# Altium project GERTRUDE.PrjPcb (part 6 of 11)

## Sheet AUDIO_CODEC.SchDoc: AUDIO CODEC
size A3; Author: Silvio Navaretti; CompanyName: ARDUINO; DrawnBy: Silvio Navaretti; Engineer: Silvio Navaretti; Organization: ARDUINO; SheetNumber: 47; SheetTotal: 51; RevAuthor: Silvio Navaretti
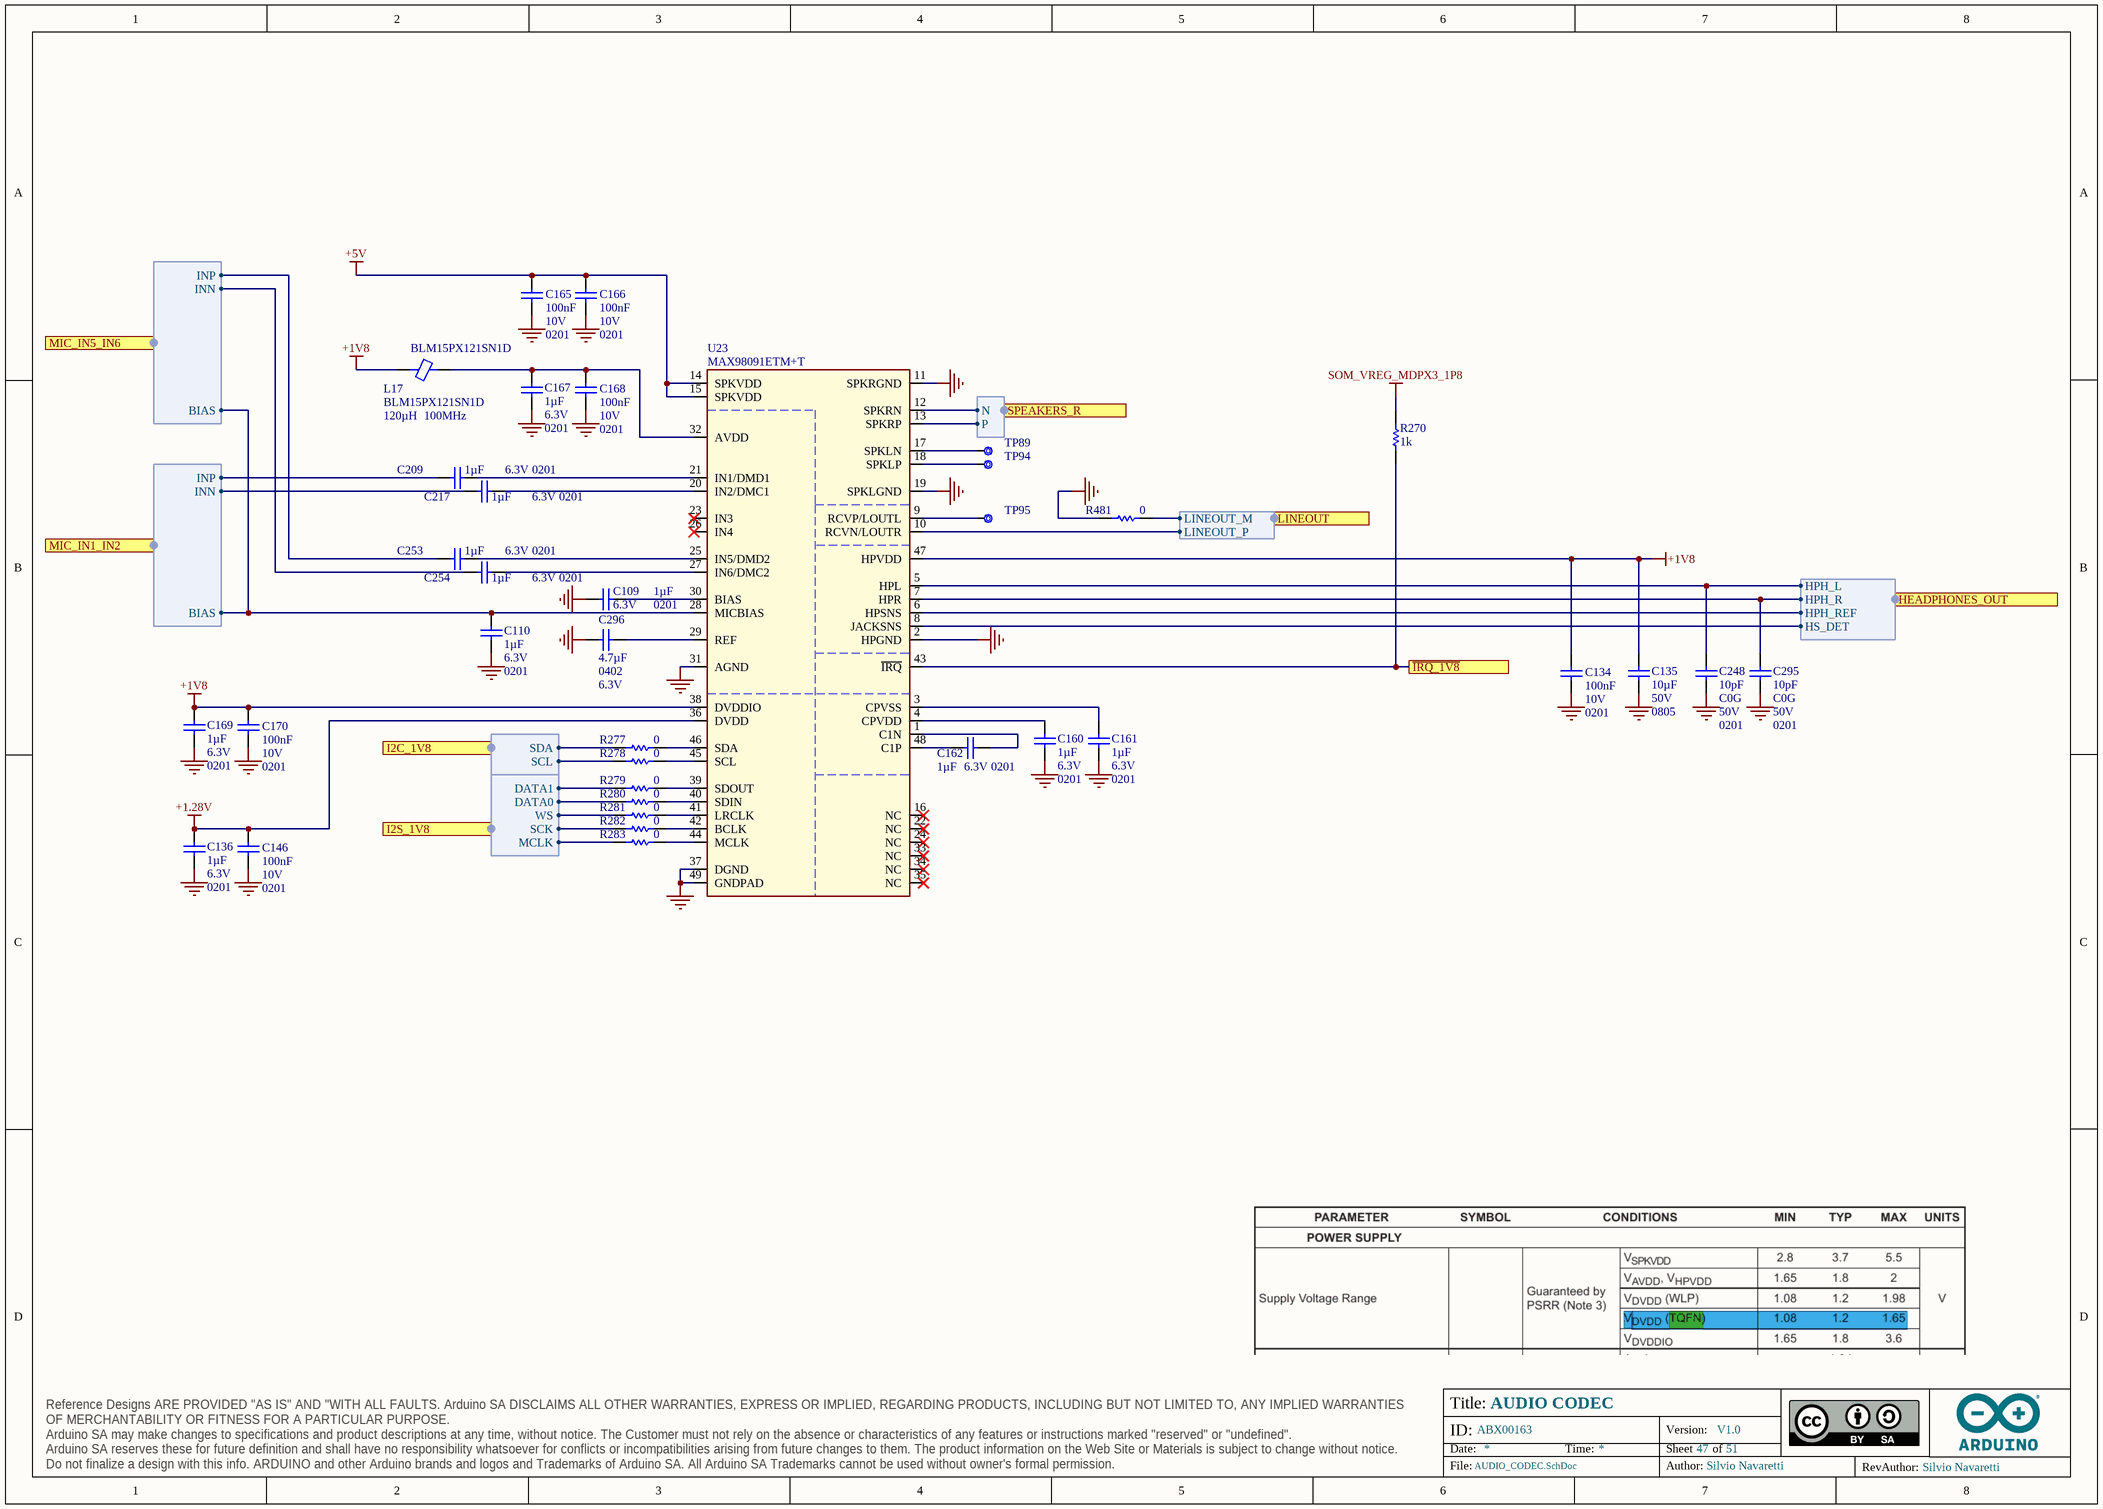
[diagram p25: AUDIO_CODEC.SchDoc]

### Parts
C109  value 1µF  Voltage: 6.3V  Case Code (Imperial): 0201  [CAP-0201]  (hidden comment: GRM033R60J105MEA2D)
C110  value 1µF  Voltage: 6.3V  Case Code (Imperial): 0201  [CAP-0201]  (hidden comment: GRM033R60J105MEA2D)
C134  value 100nF  Voltage: 10V  Case Code (Imperial): 0201  [CAP-0201]  (hidden comment: CL03A104KP3NNNC)
C135  value 10µF  Voltage: 50V  Case Code (Imperial): 0805  [CAP-0805]  (hidden comment: GRM21BR61H106ME43L)
C136  value 1µF  Voltage: 6.3V  Case Code (Imperial): 0201  [CAP-0201]  (hidden comment: GRM033R60J105MEA2D)
C146  value 100nF  Voltage: 10V  Case Code (Imperial): 0201  [CAP-0201]  (hidden comment: CL03A104KP3NNNC)
C160  value 1µF  Voltage: 6.3V  Case Code (Imperial): 0201  [CAP-0201]  (hidden comment: GRM033R60J105MEA2D)
C161  value 1µF  Voltage: 6.3V  Case Code (Imperial): 0201  [CAP-0201]  (hidden comment: GRM033R60J105MEA2D)
C162  value 1µF  Voltage: 6.3V  Case Code (Imperial): 0201  [CAP-0201]  (hidden comment: GRM033R60J105MEA2D)
C165  value 100nF  Voltage: 10V  Case Code (Imperial): 0201  [CAP-0201]  (hidden comment: CL03A104KP3NNNC)
C166  value 100nF  Voltage: 10V  Case Code (Imperial): 0201  [CAP-0201]  (hidden comment: CL03A104KP3NNNC)
C167  value 1µF  Voltage: 6.3V  Case Code (Imperial): 0201  [CAP-0201]  (hidden comment: GRM033R60J105MEA2D)
C168  value 100nF  Voltage: 10V  Case Code (Imperial): 0201  [CAP-0201]  (hidden comment: CL03A104KP3NNNC)
C169  value 1µF  Voltage: 6.3V  Case Code (Imperial): 0201  [CAP-0201]  (hidden comment: GRM033R60J105MEA2D)
C170  value 100nF  Voltage: 10V  Case Code (Imperial): 0201  [CAP-0201]  (hidden comment: CL03A104KP3NNNC)
C209  value 1µF  Voltage: 6.3V  Case Code (Imperial): 0201  [CAP-0201]  (hidden comment: GRM033R60J105MEA2D)
C217  value 1µF  Voltage: 6.3V  Case Code (Imperial): 0201  [CAP-0201]  (hidden comment: GRM033R60J105MEA2D)
C248  value 10pF  Dielectric: C0G  Voltage: 50V  Case Code (Imperial): 0201  [CAP-0201]  (hidden comment: CC0201GRNPO9BN100)
C253  value 1µF  Voltage: 6.3V  Case Code (Imperial): 0201  [CAP-0201]  (hidden comment: GRM033R60J105MEA2D)
C254  value 1µF  Voltage: 6.3V  Case Code (Imperial): 0201  [CAP-0201]  (hidden comment: GRM033R60J105MEA2D)
C295  value 10pF  Dielectric: C0G  Voltage: 50V  Case Code (Imperial): 0201  [CAP-0201]  (hidden comment: CC0201GRNPO9BN100)
C296  value 4.7µF  Case Code (Imperial): 0402  Voltage: 6.3V  [CAP-0402]  (hidden comment: C1005A475M6R3NT)
L17  BLM15PX121SN1D  Inductance: 120µH  Test Frequency: 100MHz  [L-0402]
R270  value 1k  [RES-0201]  (hidden comment: RC0201FR-071KL)
R277  value 0  [RES-0201]  (hidden comment: CRCW02010000Z0ED)
R278  value 0  [RES-0201]  (hidden comment: CRCW02010000Z0ED)
R279  value 0  [RES-0201]  (hidden comment: CRCW02010000Z0ED)
R280  value 0  [RES-0201]  (hidden comment: CRCW02010000Z0ED)
R281  value 0  [RES-0201]  (hidden comment: CRCW02010000Z0ED)
R282  value 0  [RES-0201]  (hidden comment: CRCW02010000Z0ED)
R283  value 0  [RES-0201]  (hidden comment: CRCW02010000Z0ED)
R481  value 0  [RES-0201]  (hidden comment: CRCW02010000Z0ED)
TP89  Test point 1.00mm  [TP-1.00MM]  (value not drawn)  (no BOM)
TP94  Test point 1.00mm  [TP-1.00MM]  (value not drawn)  (no BOM)
TP95  Test point 1.00mm  [TP-1.00MM]  (value not drawn)  (no BOM)
U23  MAX98091ETM+T  [QFN127P600-8N]

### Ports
HEADPHONES_OUT (harness HEADPHONES), I2C_1V8 (harness I2C), I2S_1V8 (harness SOM_MD_I2S_QUA), LINEOUT (harness LINEOUT), MIC_IN1_IN2 (harness MIC), MIC_IN5_IN6 (harness MIC), SPEAKERS_R (harness SPEAKERS), ~{IRQ_1V8}

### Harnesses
I2C: SDA, SCL
HEADPHONES: HPH_L, HPH_R, HPH_REF, HS_DET
MIC: INP, INN, BIAS
SPEAKERS: N, P
SOM_MD_I2S_QUA: SCK, WS, DATA0, DATA1, MCLK
LINEOUT: LINEOUT_P, LINEOUT_M

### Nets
+1.28V: C136.2 C146.2 U23.36(DVDD)
+1V8: C134.2 C135.1 C169.2 C170.2 L17.1 U23.38(DVDDIO) U23.47(HPVDD)
+5V: C165.2 C166.2 U23.14(SPKVDD) U23.15(SPKVDD)
GND: C109.1 C110.1 C134.1 C135.2 C136.1 C146.1 C160.1 C161.1 C165.1 C166.1 C167.1 C168.1 C169.1 C170.1 C248.1 C295.1 C296.2 R481.1 U23.2(HPGND) U23.11(SPKRGND) U23.19(SPKLGND) U23.31(AGND) U23.37(DGND) U23.49(GNDPAD)
SOM_VREG_MDPX3_1P8: R270.2
MD_GPIO_16: R270.1 U23.43(~{IRQ}) ; port ~{IRQ_1V8}
MD_GPIO_45: R277.1 ; port I2C_1V8.SDA
MD_GPIO_46: R278.1 ; port I2C_1V8.SCL
MD_LPASS_GPIO_110: R282.1 ; port I2S_1V8.SCK
MD_LPASS_GPIO_111: R281.1 ; port I2S_1V8.WS
MD_LPASS_GPIO_112: R280.1 ; port I2S_1V8.DATA0
MD_LPASS_GPIO_113: R279.1 ; port I2S_1V8.DATA1
MD_LPASS_GPIO_115: R283.1 ; port I2S_1V8.MCLK
MIC_IN5_IN6.BIAS: C110.2 U23.28(MICBIAS) ; port MIC_IN1_IN2.BIAS, port MIC_IN5_IN6.BIAS
MIC_IN5_IN6.INN: C254.2 ; port MIC_IN5_IN6.INN
MIC_IN5_IN6.INP: C253.2 ; port MIC_IN5_IN6.INP
NetC109_2: C109.2 U23.30(BIAS)
NetC160_2: C160.2 U23.4(CPVDD)
NetC161_2: C161.2 U23.3(CPVSS)
NetC162_1: C162.1 U23.1(C1N)
NetC162_2: C162.2 U23.48(C1P)
NetC167_2: C167.2 C168.2 L17.2 U23.32(AVDD)
NetC209_1: C209.1 U23.21(IN1/DMD1)
NetC209_2: C209.2 ; port MIC_IN1_IN2.INP
NetC217_1: C217.1 U23.20(IN2/DMC1)
NetC217_2: C217.2 ; port MIC_IN1_IN2.INN
NetC248_2: C248.2 U23.5(HPL) ; port HEADPHONES_OUT.HPH_L
NetC253_1: C253.1 U23.25(IN5/DMD2)
NetC254_1: C254.1 U23.27(IN6/DMC2)
NetC295_2: C295.2 U23.7(HPR) ; port HEADPHONES_OUT.HPH_R
NetC296_1: C296.1 U23.29(REF)
NetD103_1: U23.13(SPKRP) ; port SPEAKERS_R.P
NetD103_2: U23.12(SPKRN) ; port SPEAKERS_R.N
NetD103_4: U23.10(RCVN/LOUTR) ; port LINEOUT.LINEOUT_P
NetD103_5: R481.2 ; port LINEOUT.LINEOUT_M
NetD104_4: U23.6(HPSNS) ; port HEADPHONES_OUT.HPH_REF
NetD104_5: U23.8(JACKSNS) ; port HEADPHONES_OUT.HS_DET
NetR277_2: R277.2 U23.46(SDA)
NetR278_2: R278.2 U23.45(SCL)
NetR279_2: R279.2 U23.39(SDOUT)
NetR280_2: R280.2 U23.40(SDIN)
NetR281_2: R281.2 U23.41(LRCLK)
NetR282_2: R282.2 U23.42(BCLK)
NetR283_2: R283.2 U23.44(MCLK)
NetTP89_X: TP89.X U23.17(SPKLN)
NetTP94_X: TP94.X U23.18(SPKLP)
NetTP95_X: TP95.X U23.9(RCVP/LOUTL)

Not connected (* = marked no-connect by the designer): U23 16(NC)* 22(NC)* 23(IN3)* 24(NC)* 26(IN4)* 33(NC)* 34(NC)* 35(NC)*

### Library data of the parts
C109 C110 C136 C160-C162 C167 C169 C209 C217 C253 C254 = C0002-A.15: CAP CHIP 0201 1uF 20% 6.3V X5R; Manufacturer: Murata; Code Arduino: A5520
C134 C146 C165 C166 C168 C170 = C0113-A.6: CAP CHIP 0201 100nF 10% 10V X5R; Manufacturer: Samsung Electro-Mechanics; Code Arduino: C0113
C135 = C0158-A.3: CAP CHIP 0805 10uF 20% 50V X5R; Manufacturer: Murata Electronics; Code Arduino: C0158
C248 C295 = C0144-A.3: CAP CHIP 0201 10pF 5% 50V C0G; Manufacturer: Yageo; Code Arduino: C0144
C296 = C0037-A.14: CAP CHIP 0402 4.7uF 20% 6V3 X5R; Manufacturer: Hottech; Code Arduino: 0833
L17 = I0028-A.10: FERRITE SMD 0402 120Ohm 25% 100MHz Ferrite 2A; Manufacturer: Murata; DC Resistance (DCR): 55mR; Code Arduino: I0028; Value: 120µH
R270 = R0195-A.22: RES CHIP 0201 1k 1% 1/20W; Manufacturer: Yageo; Power: 50mW; Temperature coefficient: 200ppm; Code Arduino: R0195
R277-R283 R481 = R0140-A.21: RES CHIP 0201 0R; Manufacturer: Vishay; Temperature coefficient: 0ppm; Code Arduino: R0140; Power: 50mW; Tolerance: 0%
TP89 TP94 TP95 = UT0013-A.6: Part Number: This is not a component
U23 = U0313-A.5: CODEC Audio CODEC, 4 IN microphone, stereo speaker out 3.2W, stereo headphone out, line output, I2C+I2S, QFN48 6x6; Manufacturer: Analog Devices; Code Arduino: U0313

## Sheet HEADERS_JHAT.SchDoc: HEADERS JHAT
size A3; Author: Silvio Navaretti; CompanyName: ARDUINO; DrawnBy: Silvio Navaretti; Engineer: Silvio Navaretti; Organization: ARDUINO; SheetNumber: 20; SheetTotal: 51; RevAuthor: Silvio Navaretti
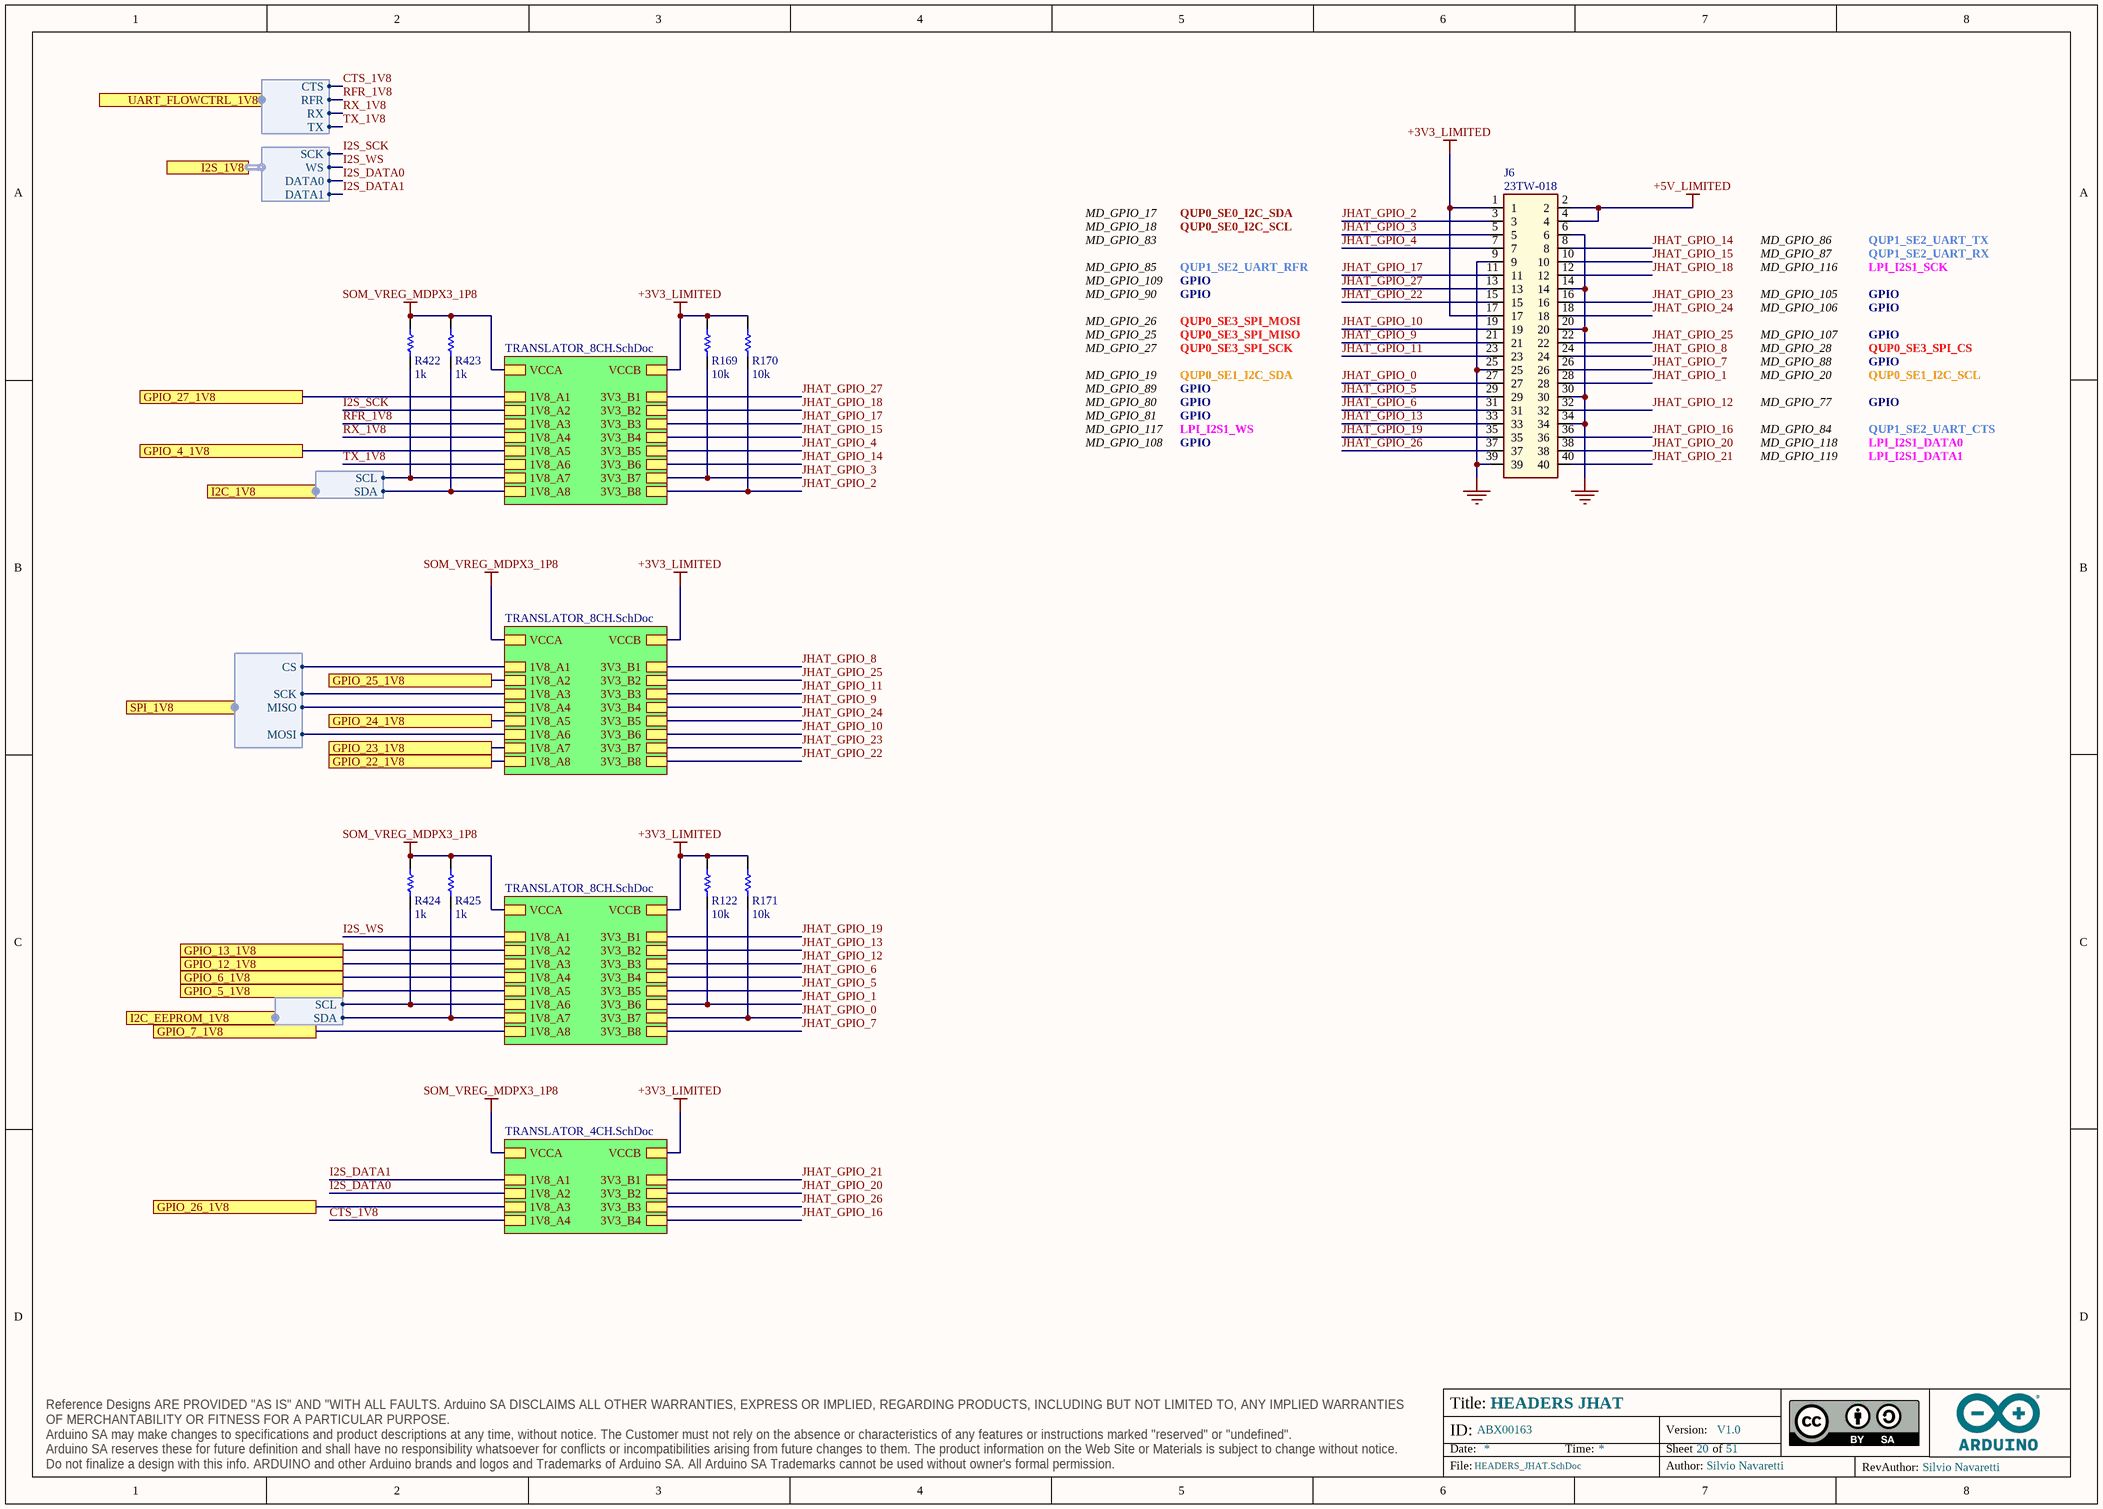
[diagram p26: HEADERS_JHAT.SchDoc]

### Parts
J6  23TW-018  [23TW-018]
R122  value 10k  [RES-0201]  (hidden comment: RC0201FR-0710KL)
R169  value 10k  [RES-0201]  (hidden comment: RC0201FR-0710KL)
R170  value 10k  [RES-0201]  (hidden comment: RC0201FR-0710KL)
R171  value 10k  [RES-0201]  (hidden comment: RC0201FR-0710KL)
R422  value 1k  [RES-0201]  (hidden comment: RC0201FR-071KL)
R423  value 1k  [RES-0201]  (hidden comment: RC0201FR-071KL)
R424  value 1k  [RES-0201]  (hidden comment: RC0201FR-071KL)
R425  value 1k  [RES-0201]  (hidden comment: RC0201FR-071KL)

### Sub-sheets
T8CH_ = TRANSLATOR_8CH.SchDoc: 1V8_A1, 1V8_A2, 1V8_A3, 1V8_A4, 1V8_A5, 1V8_A6, 1V8_A7, 1V8_A8, 3V3_B1, 3V3_B2, 3V3_B3, 3V3_B4, 3V3_B5, 3V3_B6, 3V3_B7, VCCA, VCCB, 3V3_B8
T8CH_ = TRANSLATOR_8CH.SchDoc: 1V8_A1, 1V8_A2, 1V8_A3, 1V8_A4, 1V8_A5, 1V8_A6, 1V8_A7, 1V8_A8, 3V3_B1, 3V3_B2, 3V3_B3, 3V3_B4, 3V3_B5, 3V3_B6, 3V3_B7, 3V3_B8, VCCA, VCCB
T8CH_ = TRANSLATOR_8CH.SchDoc: 1V8_A1, 1V8_A2, 1V8_A3, 1V8_A4, 1V8_A5, 1V8_A6, 1V8_A7, 1V8_A8, 3V3_B1, 3V3_B2, 3V3_B3, 3V3_B4, 3V3_B5, 3V3_B6, 3V3_B7, 3V3_B8, VCCA, VCCB
U_TRANSLATOR_4CH = TRANSLATOR_4CH.SchDoc: 1V8_A1, 1V8_A2, 1V8_A3, 1V8_A4, 3V3_B1, 3V3_B2, 3V3_B3, 3V3_B4, VCCA, VCCB

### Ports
GPIO_4_1V8, GPIO_5_1V8, GPIO_6_1V8, GPIO_7_1V8, GPIO_12_1V8, GPIO_13_1V8, GPIO_22_1V8, GPIO_23_1V8, GPIO_24_1V8, GPIO_25_1V8, GPIO_26_1V8, GPIO_27_1V8, I2C_1V8 (harness I2C), I2C_EEPROM_1V8 (harness I2C), I2S_1V8 (harness SOM_MD_I2S), SPI_1V8 (harness SPI), UART_FLOWCTRL_1V8 (harness SOM_MD_UART_FLCRTL)

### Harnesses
I2C: SDA, SCL
SPI: SCK, MISO, MOSI, CS
SOM_MD_UART_FLCRTL: TX, CTS, RFR, RX
SOM_MD_I2S: SCK, WS, DATA0, DATA1

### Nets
+3V3_LIMITED: J6.1 J6.17 R122.1 R169.1 R170.1 R171.1 ; sheet T8CH_/VCCB, sheet T8CH_/VCCB, sheet T8CH_/VCCB, sheet U_TRANSLATOR_4CH/VCCB
+5V_LIMITED: J6.2 J6.4
GND: J6.6 J6.9 J6.14 J6.20 J6.25 J6.30 J6.34 J6.39
SOM_VREG_MDPX3_1P8: R422.1 R423.1 R424.1 R425.1 ; sheet T8CH_/VCCA, sheet T8CH_/VCCA, sheet T8CH_/VCCA, sheet U_TRANSLATOR_4CH/VCCA
CTS_1V8: sheet U_TRANSLATOR_4CH/1V8_A4, port UART_FLOWCTRL_1V8.CTS
I2S_DATA0: sheet U_TRANSLATOR_4CH/1V8_A2, port I2S_1V8.DATA0
I2S_DATA1: sheet U_TRANSLATOR_4CH/1V8_A1, port I2S_1V8.DATA1
I2S_SCK: sheet T8CH_/1V8_A2, port I2S_1V8.SCK
I2S_WS: sheet T8CH_/1V8_A1, port I2S_1V8.WS
JHAT_GPIO_0: J6.27 R171.2 ; sheet T8CH_/3V3_B7
JHAT_GPIO_1: J6.28 R122.2 ; sheet T8CH_/3V3_B6
JHAT_GPIO_2: J6.3 R170.2 ; sheet T8CH_/3V3_B8
JHAT_GPIO_3: J6.5 R169.2 ; sheet T8CH_/3V3_B7
JHAT_GPIO_4: J6.7 ; sheet T8CH_/3V3_B5
JHAT_GPIO_5: J6.29 ; sheet T8CH_/3V3_B5
JHAT_GPIO_6: J6.31 ; sheet T8CH_/3V3_B4
JHAT_GPIO_7: J6.26 ; sheet T8CH_/3V3_B8
JHAT_GPIO_8: J6.24 ; sheet T8CH_/3V3_B1
JHAT_GPIO_9: J6.21 ; sheet T8CH_/3V3_B4
JHAT_GPIO_10: J6.19 ; sheet T8CH_/3V3_B6
JHAT_GPIO_11: J6.23 ; sheet T8CH_/3V3_B3
JHAT_GPIO_12: J6.32 ; sheet T8CH_/3V3_B3
JHAT_GPIO_13: J6.33 ; sheet T8CH_/3V3_B2
JHAT_GPIO_14: J6.8 ; sheet T8CH_/3V3_B6
JHAT_GPIO_15: J6.10 ; sheet T8CH_/3V3_B4
JHAT_GPIO_16: J6.36 ; sheet U_TRANSLATOR_4CH/3V3_B4
JHAT_GPIO_17: J6.11 ; sheet T8CH_/3V3_B3
JHAT_GPIO_18: J6.12 ; sheet T8CH_/3V3_B2
JHAT_GPIO_19: J6.35 ; sheet T8CH_/3V3_B1
JHAT_GPIO_20: J6.38 ; sheet U_TRANSLATOR_4CH/3V3_B2
JHAT_GPIO_21: J6.40 ; sheet U_TRANSLATOR_4CH/3V3_B1
JHAT_GPIO_22: J6.15 ; sheet T8CH_/3V3_B8
JHAT_GPIO_23: J6.16 ; sheet T8CH_/3V3_B7
JHAT_GPIO_24: J6.18 ; sheet T8CH_/3V3_B5
JHAT_GPIO_25: J6.22 ; sheet T8CH_/3V3_B2
JHAT_GPIO_26: J6.37 ; sheet U_TRANSLATOR_4CH/3V3_B3
JHAT_GPIO_27: J6.13 ; sheet T8CH_/3V3_B1
MD_GPIO_17: R423.2 ; sheet T8CH_/1V8_A8, port I2C_1V8.SDA
MD_GPIO_18: R422.2 ; sheet T8CH_/1V8_A7, port I2C_1V8.SCL
MD_GPIO_19: R425.2 ; sheet T8CH_/1V8_A7, port I2C_EEPROM_1V8.SDA
MD_GPIO_20: R424.2 ; sheet T8CH_/1V8_A6, port I2C_EEPROM_1V8.SCL
MD_GPIO_25: sheet T8CH_/1V8_A4, port SPI_1V8.MISO
MD_GPIO_26: sheet T8CH_/1V8_A6, port SPI_1V8.MOSI
MD_GPIO_27: sheet T8CH_/1V8_A3, port SPI_1V8.SCK
MD_GPIO_28: sheet T8CH_/1V8_A1, port SPI_1V8.CS
MD_GPIO_77: port GPIO_12_1V8, sheet T8CH_/1V8_A3
MD_GPIO_80: port GPIO_6_1V8, sheet T8CH_/1V8_A4
MD_GPIO_81: port GPIO_13_1V8, sheet T8CH_/1V8_A2
MD_GPIO_83: port GPIO_4_1V8, sheet T8CH_/1V8_A5
MD_GPIO_88: port GPIO_7_1V8, sheet T8CH_/1V8_A8
MD_GPIO_89: port GPIO_5_1V8, sheet T8CH_/1V8_A5
MD_GPIO_90: port GPIO_22_1V8, sheet T8CH_/1V8_A8
MD_GPIO_105: port GPIO_23_1V8, sheet T8CH_/1V8_A7
MD_GPIO_106: port GPIO_24_1V8, sheet T8CH_/1V8_A5
MD_GPIO_107: port GPIO_25_1V8, sheet T8CH_/1V8_A2
MD_GPIO_108: port GPIO_26_1V8, sheet U_TRANSLATOR_4CH/1V8_A3
MD_GPIO_109: port GPIO_27_1V8, sheet T8CH_/1V8_A1
RFR_1V8: sheet T8CH_/1V8_A3, port UART_FLOWCTRL_1V8.RFR  [project net MD_GPIO_85]
RX_1V8: sheet T8CH_/1V8_A4, port UART_FLOWCTRL_1V8.RX  [project net MD_GPIO_87]
TX_1V8: sheet T8CH_/1V8_A6, port UART_FLOWCTRL_1V8.TX  [project net MD_GPIO_86]

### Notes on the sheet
- MD_GPIO_17
- MD_GPIO_18
- MD_GPIO_83
- QUP0_SE0_I2C_SDA
- QUP0_SE0_I2C_SCL
- MD_GPIO_86
- QUP1_SE2_UART_TX
- MD_GPIO_85
- MD_GPIO_109
- MD_GPIO_90
- QUP1_SE2_UART_RFR
- GPIO
- MD_GPIO_87
- MD_GPIO_116
- MD_GPIO_105
- MD_GPIO_106
- QUP1_SE2_UART_RX
- LPI_I2S1_SCK
- MD_GPIO_26
- MD_GPIO_25
- MD_GPIO_27
- MD_GPIO_19
- QUP0_SE3_SPI_MOSI
- QUP0_SE3_SPI_MISO
- QUP0_SE3_SPI_SCK
- QUP0_SE1_I2C_SDA
- MD_GPIO_107
- MD_GPIO_28
- MD_GPIO_88
- MD_GPIO_20
- QUP0_SE3_SPI_CS
- QUP0_SE1_I2C_SCL
- MD_GPIO_89
- MD_GPIO_80
- MD_GPIO_81
- MD_GPIO_117
- MD_GPIO_108
- LPI_I2S1_WS
- MD_GPIO_77
- MD_GPIO_84
- MD_GPIO_118
- QUP1_SE2_UART_CTS
- LPI_I2S1_DATA0
- MD_GPIO_119
- LPI_I2S1_DATA1

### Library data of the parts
J6 = J0572-A.1: CONN HEADER MALE 40POS 2x20 2.54mm SMD 6mm pin length; Manufacturer: 4UCONN; Code Arduino: J0572; Connector Type: BOARD CONNECTOR; Number of Contacts: 40
R122 R169-R171 = R0145-A.21: RES CHIP 0201 10k 1% 1/20W; Manufacturer: Yageo; Power: 50mW; Temperature coefficient: 200ppm; Code Arduino: R0145
R422-R425 = R0195-A.22: as R270 on sheet AUDIO_CODEC

## Sheet TRANSLATOR_4CH.SchDoc: TRANSLATOR 4CH
size A4; Author: Silvio Navaretti; CompanyName: ARDUINO; DrawnBy: Silvio Navaretti; Engineer: Silvio Navaretti; Organization: ARDUINO; SheetNumber: 18; SheetTotal: 51; RevAuthor: Silvio Navaretti
Used 5 times, as channels U_HEADERS_JHAT/U_TRANSLATOR_4CH, U_MIPI/U_TRANSLATOR_4CH, U_MICROCONTROLLER/U_TRANSLATOR_4CH, U_PCIE/U_WIFI_BLE/U_TRANSLATOR_4CH, U_PCIE/U_TRANSLATOR_4CH. Parts and nets are listed once, with the designators drawn on the sheet.
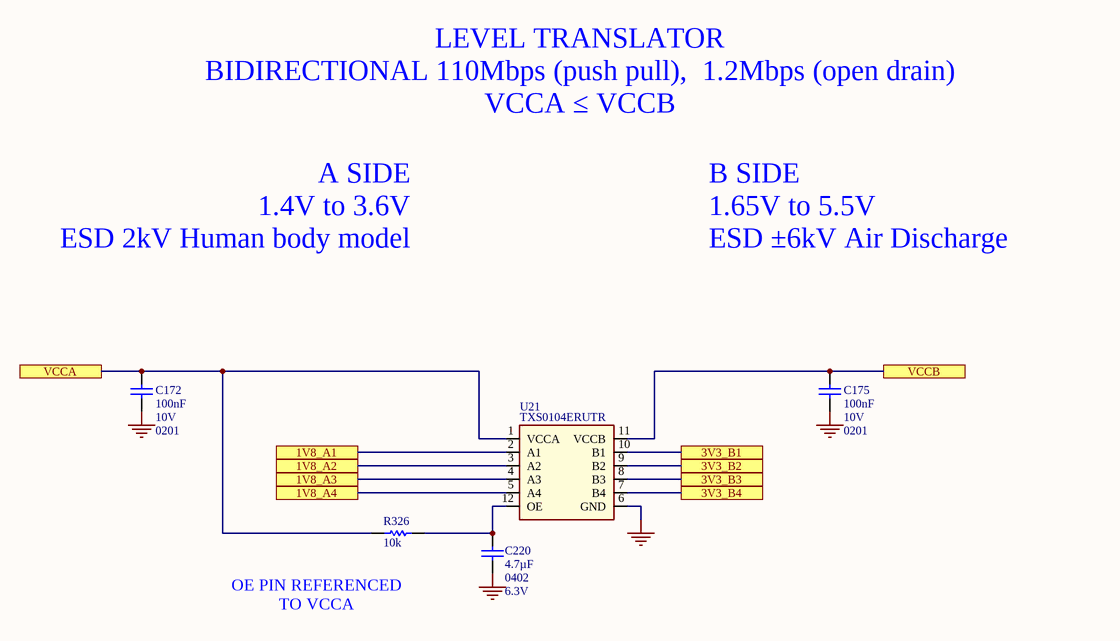
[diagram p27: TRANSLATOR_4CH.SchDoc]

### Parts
C172  value 100nF  Voltage: 10V  Case Code (Imperial): 0201  [CAP-0201]  (hidden comment: CL03A104KP3NNNC)
C175  value 100nF  Voltage: 10V  Case Code (Imperial): 0201  [CAP-0201]  (hidden comment: CL03A104KP3NNNC)
C220  value 4.7µF  Case Code (Imperial): 0402  Voltage: 6.3V  [CAP-0402]  (hidden comment: C1005A475M6R3NT)
R326  value 10k  [RES-0201]  (hidden comment: RC0201FR-0710KL)
U21  TXS0104ERUTR  [TI RUT RUT0012A UQFN 2x1.7x0.55mm 12 pins 0.4mm pitch]

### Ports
1V8_A1, 1V8_A2, 1V8_A3, 1V8_A4, 3V3_B1, 3V3_B2, 3V3_B3, 3V3_B4, VCCA, VCCB

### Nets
GND: C172.1 C175.1 C220.2 U21.6(GND)
1V8_A1: U21.2(A1) ; port 1V8_A1
1V8_A2: U21.3(A2) ; port 1V8_A2
1V8_A3: U21.4(A3) ; port 1V8_A3
1V8_A4: U21.5(A4) ; port 1V8_A4
3V3_B1: U21.10(B1) ; port 3V3_B1
3V3_B2: U21.9(B2) ; port 3V3_B2
3V3_B3: U21.8(B3) ; port 3V3_B3
3V3_B4: U21.7(B4) ; port 3V3_B4
VCCA: C172.2 R326.2 U21.1(VCCA) ; port VCCA
VCCB: C175.2 U21.11(VCCB) ; port VCCB
NetC220_1: C220.1 R326.1 U21.12(OE)

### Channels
U_HEADERS_JHAT/U_TRANSLATOR_4CH: designators end in _1; ports 1V8_A1=I2S_DATA1 1V8_A2=I2S_DATA0 1V8_A3=MD_GPIO_108 1V8_A4=CTS_1V8 3V3_B1=JHAT_GPIO_21 3V3_B2=JHAT_GPIO_20 3V3_B3=JHAT_GPIO_26 3V3_B4=JHAT_GPIO_16 VCCA=SOM_VREG_MDPX3_1P8 VCCB=+3V3_LIMITED
U_MIPI/U_TRANSLATOR_4CH: designators end in _2; ports 1V8_A1=MD_GPIO_64 1V8_A2=MD_GPIO_75 1V8_A3=MD_GPIO_82 1V8_A4=NetR396_2 3V3_B1=FLAT0_GPIO_PIN17_3V3 3V3_B2=FLAT1_GPIO_PIN17_3V3 3V3_B3=FLAT2_GPIO_PIN17_3V3 3V3_B4=NetR395_1 VCCA=SOM_VREG_MDPX3_1P8 VCCB=+3V3
U_MICROCONTROLLER/U_TRANSLATOR_4CH: designators end in _3; ports 1V8_A1=NetR361_1 1V8_A2=NetR362_1 1V8_A3=NetR363_1 1V8_A4=NetR364_1 3V3_B1=NetR140_2 3V3_B2=NetR151_2 3V3_B3=NetR152_2 3V3_B4=NetR153_2 VCCA=SOM_VREG_MDPX3_1P8 VCCB=+3V3
U_PCIE/U_WIFI_BLE/U_TRANSLATOR_4CH: designators end in _4; ports 1V8_A1=NetR465_1 1V8_A2=NetR23_1 1V8_A3=NetR461_2 1V8_A4=NetR429_2 3V3_B1=NetR464_2 3V3_B2=NetR463_2 3V3_B3=NetR24_2 3V3_B4=NetR428_2 VCCA=SOM_VREG_MDPX3_1P8 VCCB=+3V3
U_PCIE/U_TRANSLATOR_4CH: designators end in _5; ports 1V8_A1=GPIO_0 1V8_A2=CLKREQ_N_1V8 1V8_A3=GPIO_2 1V8_A4=NetR315_2 3V3_B1=WAKE_N_3V3 3V3_B2=CLKREQ_N_3V3 3V3_B3=RST_N_3V3 3V3_B4=NetR323_2 VCCA=SOM_VREG_MDPX3_1P8 VCCB=+3V3

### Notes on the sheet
- LEVEL TRANSLATOR
  BIDIRECTIONAL 110Mbps (push pull),  1.2Mbps (open drain)
  VCCA ≤ VCCB
- A SIDE
  1.4V to 3.6V
  ESD 2kV Human body model
- B SIDE
  1.65V to 5.5V
  ESD ±6kV Air Discharge
- (near R326) OE PIN REFERENCED TO VCCA

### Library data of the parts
C172 C175 = C0113-A.6: as C134 on sheet AUDIO_CODEC
C220 = C0037-A.14: as C296 on sheet AUDIO_CODEC
R326 = R0145-A.21: as R122 on sheet HEADERS_JHAT
U21 = U0523-A.1: IC TRANSLATOR LEVEL SHIFTER BIDIR 4b, push pull 110Mbps, open drain 1.2Mbps, VCCA 1.4V-3.6V, VCCB 1.6V-5.5V, VCCA≤VCCB, Output Enable, UQFN-12 2x1.7mm; Manufacturer: Texas Instruments; Code Arduino: U0523

## Sheet VIDEO.SchDoc: VIDEO
size A3; Author: Silvio Navaretti; CompanyName: ARDUINO; DrawnBy: Silvio Navaretti; Engineer: Silvio Navaretti; Organization: ARDUINO; SheetNumber: 41; SheetTotal: 51; RevAuthor: Silvio Navaretti
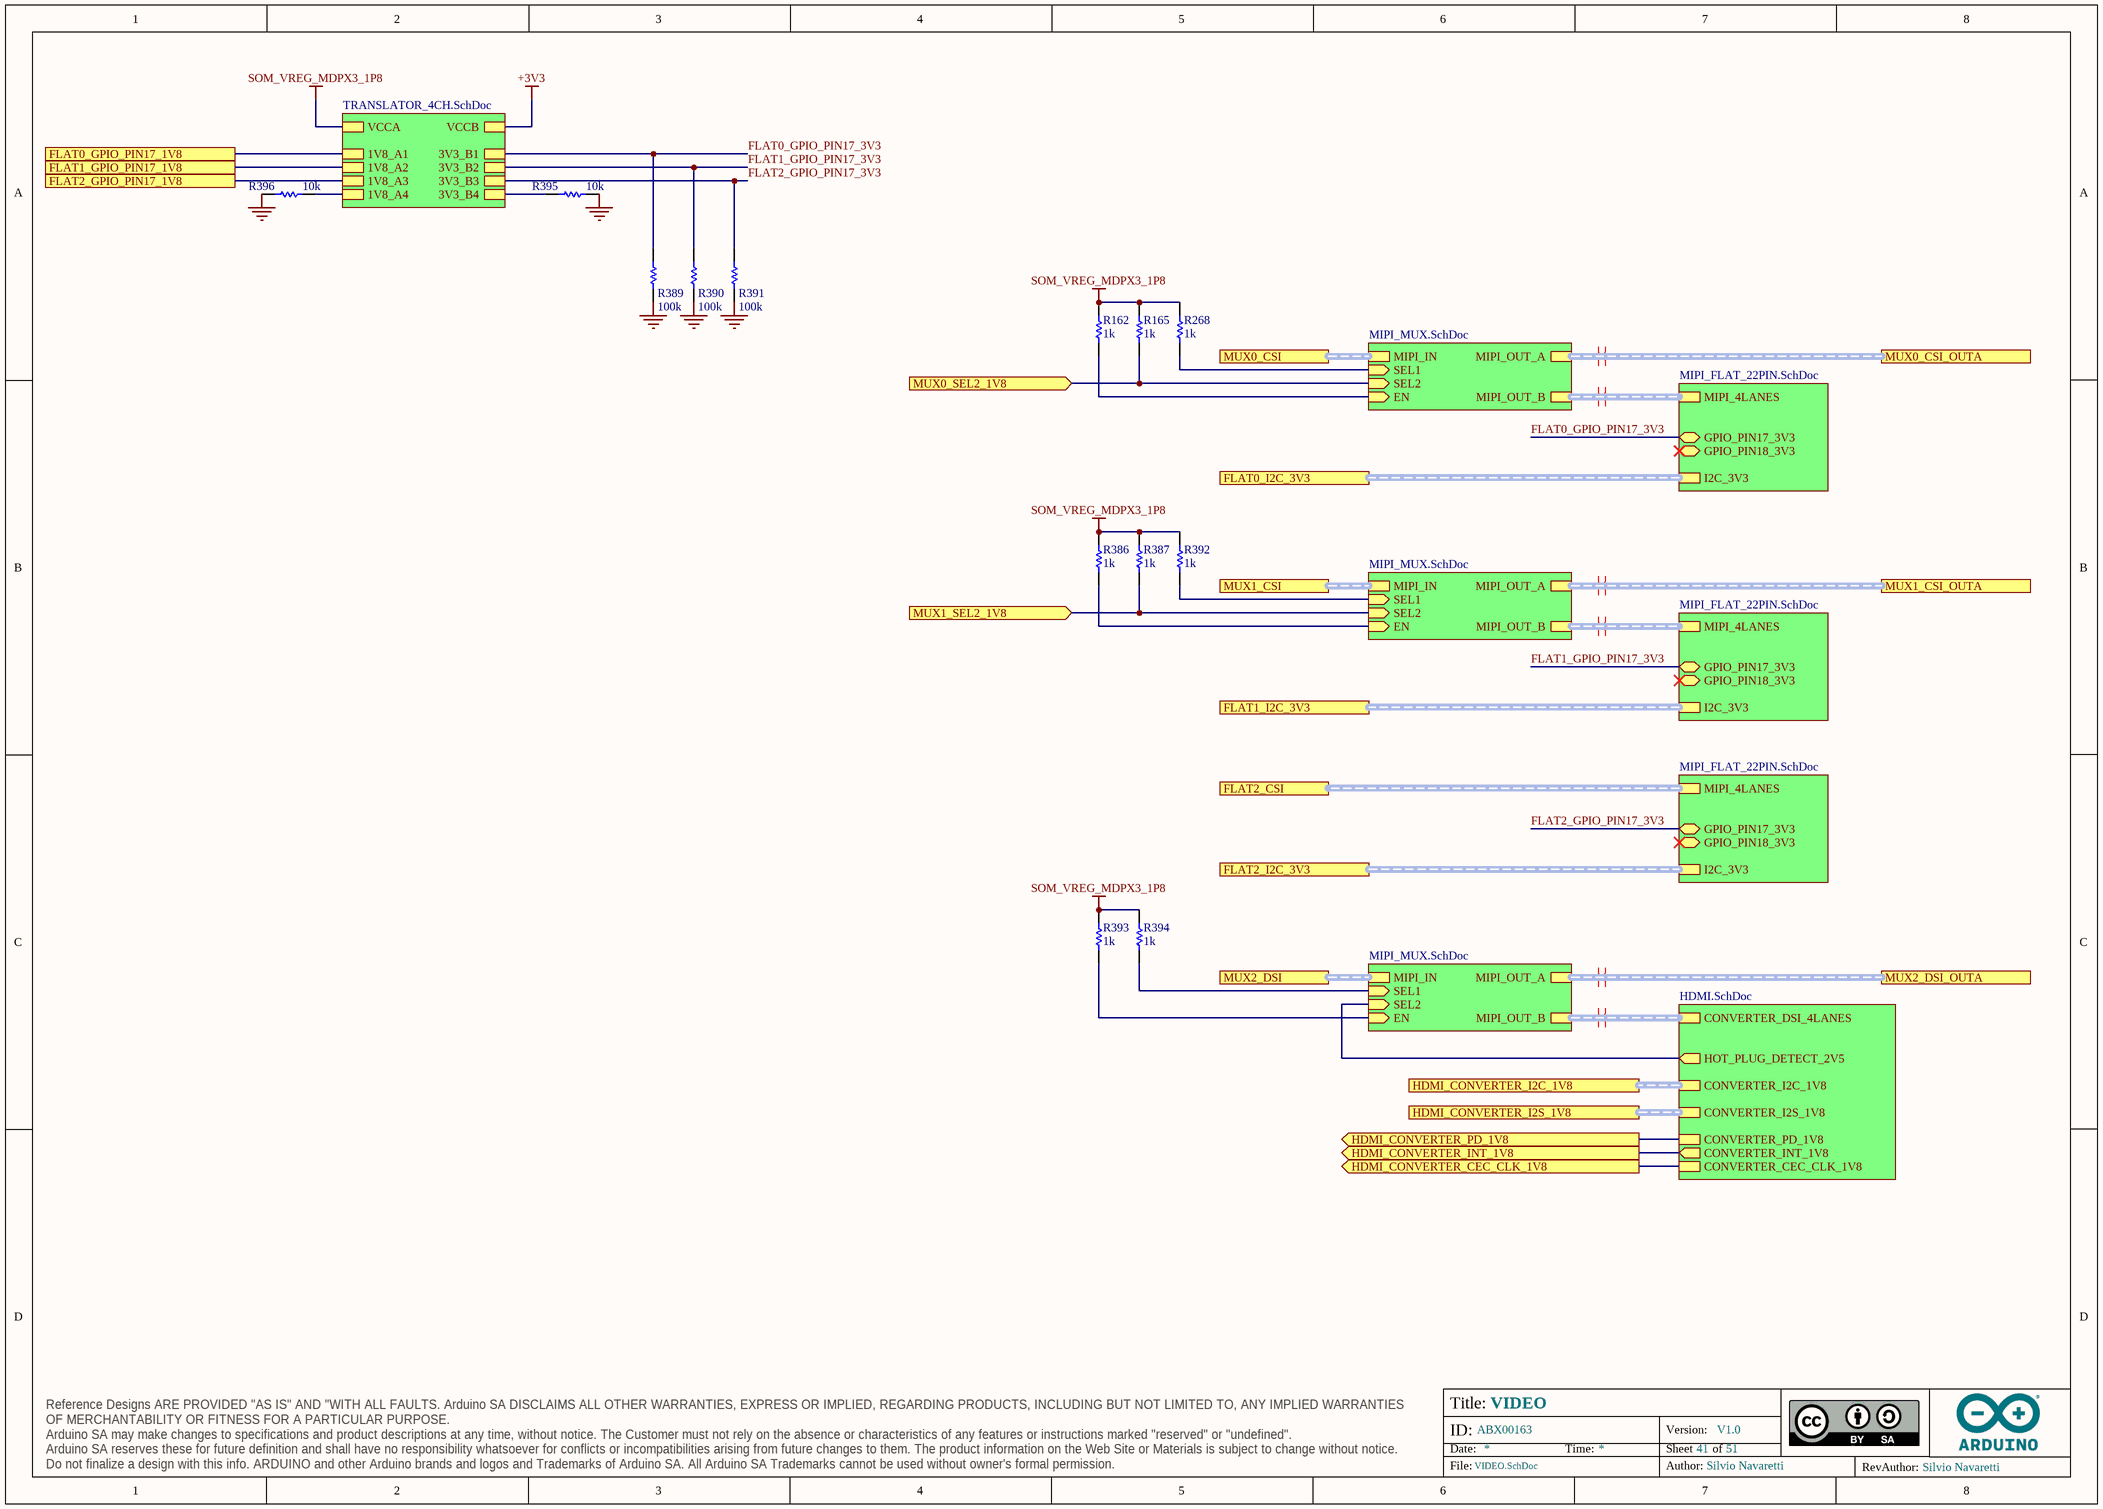
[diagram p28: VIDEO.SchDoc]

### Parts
R162  value 1k  [RES-0201]  (hidden comment: RC0201FR-071KL)
R165  value 1k  [RES-0201]  (hidden comment: RC0201FR-071KL)
R268  value 1k  [RES-0201]  (hidden comment: RC0201FR-071KL)
R386  value 1k  [RES-0201]  (hidden comment: RC0201FR-071KL)
R387  value 1k  [RES-0201]  (hidden comment: RC0201FR-071KL)
R389  value 100k  [RES-0201]  (hidden comment: RC0201FR-07100KL)
R390  value 100k  [RES-0201]  (hidden comment: RC0201FR-07100KL)
R391  value 100k  [RES-0201]  (hidden comment: RC0201FR-07100KL)
R392  value 1k  [RES-0201]  (hidden comment: RC0201FR-071KL)
R393  value 1k  [RES-0201]  (hidden comment: RC0201FR-071KL)
R394  value 1k  [RES-0201]  (hidden comment: RC0201FR-071KL)
R395  value 10k  [RES-0201]  (hidden comment: RC0201FR-0710KL)
R396  value 10k  [RES-0201]  (hidden comment: RC0201FR-0710KL)

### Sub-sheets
U_HDMI = HDMI.SchDoc: HOT_PLUG_DETECT_2V5 (out), CONVERTER_DSI_4LANES (harness MIPI_4LANES), CONVERTER_I2S_1V8 (harness MIPI_4LANES), CONVERTER_PD_1V8, CONVERTER_INT_1V8 (out), CONVERTER_CEC_CLK_1V8, CONVERTER_I2C_1V8 (harness MIPI_4LANES)
U_MIPI_FLAT_22PIN = MIPI_FLAT_22PIN.SchDoc: MIPI_4LANES (harness MIPI_4LANES), I2C_3V3 (harness I2C), GPIO_PIN17_3V3 (bidir), GPIO_PIN18_3V3 (bidir)
U_MIPI_FLAT_22PIN = MIPI_FLAT_22PIN.SchDoc: MIPI_4LANES (harness MIPI_4LANES), I2C_3V3 (harness I2C), GPIO_PIN17_3V3 (bidir), GPIO_PIN18_3V3 (bidir)
U_MIPI_FLAT_22PIN = MIPI_FLAT_22PIN.SchDoc: MIPI_4LANES (harness MIPI_4LANES), I2C_3V3 (harness I2C), GPIO_PIN17_3V3 (bidir), GPIO_PIN18_3V3 (bidir)
U_MIPI_MUX = MIPI_MUX.SchDoc: MIPI_OUT_A (harness MIPI_4LANES), MIPI_OUT_B (harness MIPI_4LANES), MIPI_IN (harness MIPI_4LANES), EN (in), SEL1 (in), SEL2 (in)
U_MIPI_MUX = MIPI_MUX.SchDoc: MIPI_IN (harness MIPI_4LANES), MIPI_OUT_A (harness MIPI_4LANES), MIPI_OUT_B (harness MIPI_4LANES), EN (in), SEL1 (in), SEL2 (in)
U_MIPI_MUX = MIPI_MUX.SchDoc: MIPI_IN (harness MIPI_4LANES), MIPI_OUT_A (harness MIPI_4LANES), MIPI_OUT_B (harness MIPI_4LANES), EN (in), SEL1 (in), SEL2 (in)
U_TRANSLATOR_4CH = TRANSLATOR_4CH.SchDoc: 1V8_A1, 1V8_A2, 1V8_A3, 1V8_A4, 3V3_B1, 3V3_B2, 3V3_B3, 3V3_B4, VCCA, VCCB

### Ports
FLAT0_GPIO_PIN17_1V8, FLAT0_I2C_3V3, FLAT1_GPIO_PIN17_1V8, FLAT1_I2C_3V3, FLAT2_CSI, FLAT2_GPIO_PIN17_1V8, FLAT2_I2C_3V3, HDMI_CONVERTER_CEC_CLK_1V8 (out), HDMI_CONVERTER_I2C_1V8 (harness I2C), HDMI_CONVERTER_I2S_1V8 (harness I2C), HDMI_CONVERTER_INT_1V8 (out), HDMI_CONVERTER_PD_1V8 (out), MUX0_CSI, MUX0_CSI_OUTA, MUX0_SEL2_1V8 (in), MUX1_CSI, MUX1_CSI_OUTA, MUX1_SEL2_1V8 (in), MUX2_DSI, MUX2_DSI_OUTA

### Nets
GND: R389.2 R390.2 R391.2 R395.2 R396.1
SOM_VREG_MDPX3_1P8: R162.1 R165.2 R268.2 R386.1 R387.2 R392.2 R393.2 R394.2 ; sheet U_TRANSLATOR_4CH/VCCA
FLAT0_GPIO_PIN17_3V3: R389.1 ; sheet U_MIPI_FLAT_22PIN/GPIO_PIN17_3V3, sheet U_TRANSLATOR_4CH/3V3_B1
FLAT1_GPIO_PIN17_3V3: R390.1 ; sheet U_MIPI_FLAT_22PIN/GPIO_PIN17_3V3, sheet U_TRANSLATOR_4CH/3V3_B2
FLAT2_GPIO_PIN17_3V3: R391.1 ; sheet U_MIPI_FLAT_22PIN/GPIO_PIN17_3V3, sheet U_TRANSLATOR_4CH/3V3_B3
MD_GPIO_24: R165.1 ; port MUX0_SEL2_1V8, sheet U_MIPI_MUX/SEL2
MD_GPIO_41: R387.1 ; port MUX1_SEL2_1V8, sheet U_MIPI_MUX/SEL2
MD_GPIO_64: port FLAT0_GPIO_PIN17_1V8, sheet U_TRANSLATOR_4CH/1V8_A1
MD_GPIO_75: port FLAT1_GPIO_PIN17_1V8, sheet U_TRANSLATOR_4CH/1V8_A2
MD_GPIO_82: port FLAT2_GPIO_PIN17_1V8, sheet U_TRANSLATOR_4CH/1V8_A3
MD_GPIO_93: port HDMI_CONVERTER_INT_1V8, sheet U_HDMI/CONVERTER_INT_1V8
NetR112_1: sheet U_HDMI/HOT_PLUG_DETECT_2V5, sheet U_MIPI_MUX/SEL2
NetR162_2: R162.2 ; sheet U_MIPI_MUX/EN
NetR268_1: R268.1 ; sheet U_MIPI_MUX/SEL1
NetR386_2: R386.2 ; sheet U_MIPI_MUX/EN
NetR392_1: R392.1 ; sheet U_MIPI_MUX/SEL1
NetR393_1: R393.1 ; sheet U_MIPI_MUX/EN
NetR394_1: R394.1 ; sheet U_MIPI_MUX/SEL1
NetR395_1: R395.1 ; sheet U_TRANSLATOR_4CH/3V3_B4
NetR396_2: R396.2 ; sheet U_TRANSLATOR_4CH/1V8_A4
NetU22_C3: port HDMI_CONVERTER_PD_1V8, sheet U_HDMI/CONVERTER_PD_1V8
NetU22_D7: port HDMI_CONVERTER_CEC_CLK_1V8, sheet U_HDMI/CONVERTER_CEC_CLK_1V8

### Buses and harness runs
harness port FLAT0_I2C_3V3 = sheet U_MIPI_FLAT_22PIN/I2C_3V3
harness port FLAT1_I2C_3V3 = sheet U_MIPI_FLAT_22PIN/I2C_3V3
harness port FLAT2_CSI = sheet U_MIPI_FLAT_22PIN/MIPI_4LANES
harness port FLAT2_I2C_3V3 = sheet U_MIPI_FLAT_22PIN/I2C_3V3
harness port HDMI_CONVERTER_I2C_1V8 = sheet U_HDMI/CONVERTER_I2C_1V8
harness port HDMI_CONVERTER_I2S_1V8 = sheet U_HDMI/CONVERTER_I2S_1V8
harness port MUX0_CSI = sheet U_MIPI_MUX/MIPI_IN
harness port MUX0_CSI_OUTA = sheet U_MIPI_MUX/MIPI_OUT_A
harness port MUX1_CSI = sheet U_MIPI_MUX/MIPI_IN
harness port MUX1_CSI_OUTA = sheet U_MIPI_MUX/MIPI_OUT_A
harness port MUX2_DSI = sheet U_MIPI_MUX/MIPI_IN
harness port MUX2_DSI_OUTA = sheet U_MIPI_MUX/MIPI_OUT_A
harness sheet U_HDMI/CONVERTER_DSI_4LANES = sheet U_MIPI_MUX/MIPI_OUT_B
harness sheet U_MIPI_FLAT_22PIN/MIPI_4LANES = sheet U_MIPI_MUX/MIPI_OUT_B

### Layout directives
differential pair; differential pair class DIFF_MUX0_OUTA; net class NET_DIFF_CSI_DSI: (no net found under the mark)
differential pair; differential pair class DIFF_MUX0_OUTB; net class NET_DIFF_CSI_DSI: (no net found under the mark)
differential pair; differential pair class DIFF_MUX1_OUTA; net class NET_DIFF_CSI_DSI: (no net found under the mark)
differential pair; differential pair class DIFF_MUX1_OUTB; net class NET_DIFF_CSI_DSI: (no net found under the mark)
differential pair; differential pair class DIFF_MUX2_OUTB; net class NET_DIFF_CSI_DSI: (no net found under the mark)
differential pair; differential pair class DIFF_MUX2_OUTA; net class NET_DIFF_CSI_DSI: (no net found under the mark)

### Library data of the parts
R162 R165 R268 R386 R387 R392-R394 = R0195-A.22: as R270 on sheet AUDIO_CODEC
R389-R391 = R0146-A.21: RES CHIP 0201 100k 1% 1/20W; Manufacturer: Yageo; Power: 50mW; Temperature coefficient: 200ppm; Code Arduino: R0146
R395 R396 = R0145-A.21: as R122 on sheet HEADERS_JHAT

## Sheet HDMI.SchDoc: HDMI
size A3; Author: Silvio Navaretti; CompanyName: ARDUINO; DrawnBy: Silvio Navaretti; Engineer: Silvio Navaretti; Organization: ARDUINO; SheetNumber: 43; SheetTotal: 50; RevAuthor: Silvio Navaretti
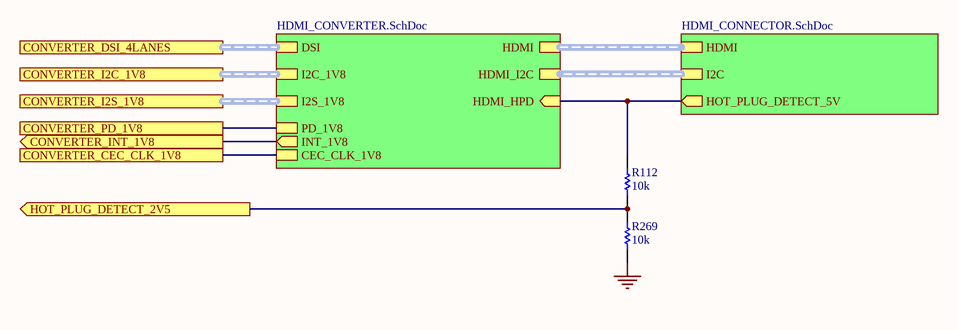
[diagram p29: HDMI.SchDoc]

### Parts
R112  value 10k  [RES-0201]  (hidden comment: RC0201FR-0710KL)
R269  value 10k  [RES-0201]  (hidden comment: RC0201FR-0710KL)

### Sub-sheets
U_HDMI_CONNECTOR = HDMI_CONNECTOR.SchDoc: HDMI (harness HDMI), I2C (harness I2C), HOT_PLUG_DETECT_5V (out)
U_HDMI_CONVERTER = HDMI_CONVERTER.SchDoc: DSI (harness MIPI_4LANES), HDMI_I2C (harness I2C), HDMI (harness HDMI), HDMI_HPD (in), I2C_1V8 (harness I2C), I2S_1V8 (harness SOM_MD_I2S), PD_1V8, INT_1V8 (out), CEC_CLK_1V8

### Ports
CONVERTER_CEC_CLK_1V8, CONVERTER_DSI_4LANES (harness MIPI_4LANES), CONVERTER_I2C_1V8 (harness MIPI_4LANES), CONVERTER_I2S_1V8 (harness MIPI_4LANES), CONVERTER_INT_1V8 (out), CONVERTER_PD_1V8, HOT_PLUG_DETECT_2V5 (out)

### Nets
GND: R269.1
MD_GPIO_93: port CONVERTER_INT_1V8, sheet U_HDMI_CONVERTER/INT_1V8
NetD16_4: R112.2 ; sheet U_HDMI_CONNECTOR/HOT_PLUG_DETECT_5V, sheet U_HDMI_CONVERTER/HDMI_HPD
NetR112_1: R112.1 R269.2 ; port HOT_PLUG_DETECT_2V5
NetU22_C3: port CONVERTER_PD_1V8, sheet U_HDMI_CONVERTER/PD_1V8
NetU22_D7: port CONVERTER_CEC_CLK_1V8, sheet U_HDMI_CONVERTER/CEC_CLK_1V8

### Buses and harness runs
harness port CONVERTER_DSI_4LANES = sheet U_HDMI_CONVERTER/DSI
harness port CONVERTER_I2C_1V8 = sheet U_HDMI_CONVERTER/I2C_1V8
harness port CONVERTER_I2S_1V8 = sheet U_HDMI_CONVERTER/I2S_1V8
harness sheet U_HDMI_CONNECTOR/HDMI = sheet U_HDMI_CONVERTER/HDMI
harness sheet U_HDMI_CONNECTOR/I2C = sheet U_HDMI_CONVERTER/HDMI_I2C

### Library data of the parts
R112 R269 = R0145-A.21: as R122 on sheet HEADERS_JHAT

## Sheet HDMI_CONNECTOR.SchDoc: HDMI CONNECTOR
size A3; Author: Silvio Navaretti; CompanyName: ARDUINO; DrawnBy: Silvio Navaretti; Engineer: Silvio Navaretti; Organization: ARDUINO; SheetNumber: 46; SheetTotal: 51; RevAuthor: Silvio Navaretti
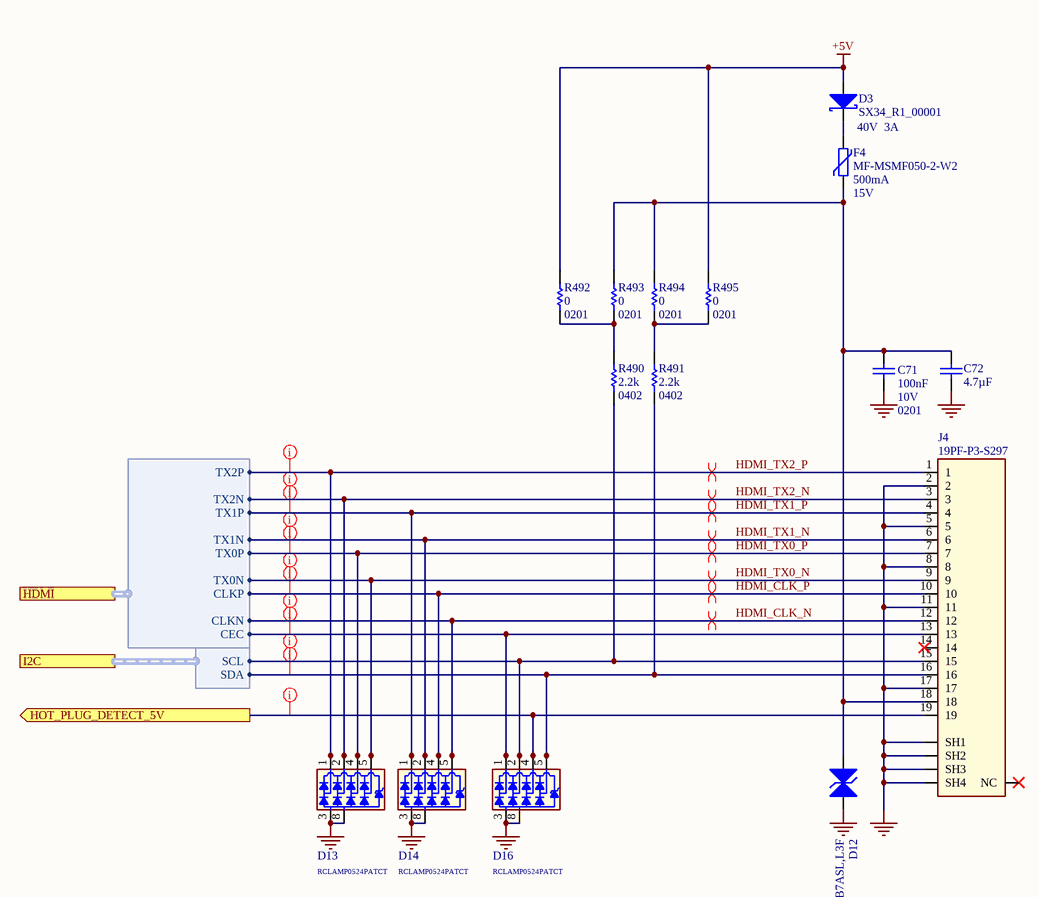
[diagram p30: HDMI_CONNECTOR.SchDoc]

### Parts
C71  value 100nF  Voltage: 10V  Case Code (Imperial): 0201  [CAP-0201]  (hidden comment: CL03A104KP3NNNC)
C72  value 4.7µF  [CAP-0402]  (hidden comment: C1005A475M6R3NT)
D3  SX34_R1_00001  Max Reverse Voltage (DC): 40V  Forward Current: 3A  [SMA DO214AC]
D12  DF2B7ASL,L3F  [DF2B7ASL,L3F]
D13  RCLAMP0524PATCT  [SLP2510P8]
D14  RCLAMP0524PATCT  [SLP2510P8]
D16  RCLAMP0524PATCT  [SLP2510P8]
F4  MF-MSMF050-2-W2  Hold Current: 500mA  Operating Supply Voltage: 15V  [1812]
J4  19PF-P3-S297  [19PF-P3-S297]
R490  value 2.2k  Case Code (Imperial): 0402  [RES-0402]  (hidden comment: AF0402FR-072K2L)
R491  value 2.2k  Case Code (Imperial): 0402  [RES-0402]  (hidden comment: AF0402FR-072K2L)
R492  value 0  Case Code (Imperial): 0201  [RES-0201]  (hidden comment: CRCW02010000Z0ED)
R493  value 0  Case Code (Imperial): 0201  [RES-0201]  (hidden comment: CRCW02010000Z0ED)
R494  value 0  Case Code (Imperial): 0201  [RES-0201]  (hidden comment: CRCW02010000Z0ED)
R495  value 0  Case Code (Imperial): 0201  [RES-0201]  (hidden comment: CRCW02010000Z0ED)

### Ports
HDMI (harness HDMI), HOT_PLUG_DETECT_5V (out), I2C (harness I2C)

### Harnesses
HDMI: TX2P, TX2N, TX1P, TX1N, TX0P, TX0N, CLKP, CLKN, CEC
I2C: SDA, SCL

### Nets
+5V: D3.A R492.2 R495.2
GND: C71.1 C72.1 D12.1(A1) D13.3 D13.8 D14.3 D14.8 D16.3 D16.8 J4.2 J4.5 J4.8 J4.11 J4.17 J4.SH1 J4.SH2 J4.SH3 J4.SH4
HDMI_CLK_N: D14.5 D14.6 J4.12 ; port HDMI.CLKN
HDMI_CLK_P: D14.4 D14.7 J4.10 ; port HDMI.CLKP
HDMI_TX0_N: D13.5 D13.6 J4.9 ; port HDMI.TX0N
HDMI_TX0_P: D13.4 D13.7 J4.7 ; port HDMI.TX0P
HDMI_TX1_N: D14.2 D14.9 J4.6 ; port HDMI.TX1N
HDMI_TX1_P: D14.1 D14.10 J4.4 ; port HDMI.TX1P
HDMI_TX2_N: D13.2 D13.9 J4.3 ; port HDMI.TX2N
HDMI_TX2_P: D13.1 D13.10 J4.1 ; port HDMI.TX2P
NetC71_2: C71.2 C72.2 D12.2(A2) F4.1 J4.18 R493.2 R494.2
NetD3_C: D3.C F4.2
NetD16_1: D16.1 D16.10 J4.13 ; port HDMI.CEC
NetD16_2: D16.2 D16.9 J4.15 R490.2 ; port I2C.SCL
NetD16_4: D16.4 D16.7 J4.19 ; port HOT_PLUG_DETECT_5V
NetD16_5: D16.5 D16.6 J4.16 R491.2 ; port I2C.SDA
NetR490_1: R490.1 R492.1 R493.1
NetR491_1: R491.1 R494.1 R495.1

Not connected (* = marked no-connect by the designer): J4 14* NC*

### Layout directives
net class NET_HDMI: HDMI_CLK_N, HDMI_CLK_P, HDMI_TX0_N, HDMI_TX0_P, HDMI_TX1_N, HDMI_TX1_P, HDMI_TX2_N, HDMI_TX2_P, NetD16_1, NetD16_2, NetD16_4, NetD16_5
differential pair; differential pair class DIFF_HDMI; net class NET_DIFF_HDMI: HDMI_CLK_N, HDMI_CLK_P, HDMI_TX0_N, HDMI_TX0_P, HDMI_TX1_N, HDMI_TX1_P, HDMI_TX2_N, HDMI_TX2_P

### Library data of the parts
C71 = C0113-A.6: as C134 on sheet AUDIO_CODEC
C72 = C0037-A.14: CAP CHIP 0402 4.7uF 20% 6V3 X5R; Manufacturer: Hottech; Code Arduino: 0833; Voltage: 6.3V
D3 = D0109-A.2: DIODE SCHOTTKY SMD 3A 40V SMA DO214AC; Part Number: SX34-AU_R1_000A1; Manufacturer: Panjit; Code Arduino: D0109; Forward Voltage: 0.39V
D12 = D0099-5: TVS BIDIRECTIONAL SMD Vr 5.5V, Vbr min 5.8V, 0.62x0.32mm; Manufacturer: TOSHIBA; Vforward max: 0V; Ireverse max: 1µA; Power max: 80W; Code Arduino: D0099; Vreverse max: 20V
D13 D14 D16 = D0097-A.6: TVS UNIDIRECTIONAL 4CH 0.8pF 5V SLP2510P8 10-pin 2.5x1.0x0.58mm; Manufacturer: SEMTECH; Code Arduino: D0097; Device Type: ESD protection
F4 = P0002-A.7: PTC RESET FUSE 15V 500MA 1812 LOGO OO ARDUINO; Manufacturer: Bourns; Approvals: UL,CSA,TUV; Time to Trip: 0.15s; Max Current Rating: 100A; Trip Current: 1A; Resistance: 150mR; Code Arduino: 3335; Power Dissipation: 800mW
J4 = J0578-A.2: CONN HDMI RIGHT ANGLE FEMALE 19 POSITIONS 7.75x23.06x16.4mm signals pins lengths 2.3mm; Manufacturer: Contact technology; Code Arduino: J0578
R490 R491 = R0286-A.3: RES CHIP 0402 2k2 1% 1/16W; Manufacturer: Yageo; Power: 62.5mW; Temperature coefficient: 100ppm; Code Arduino: R0286
R492-R495 = R0140-A.21: as R277-R283 on sheet AUDIO_CODEC

## Sheet HDMI_CONVERTER.SchDoc: HDMI CONVERTER
size A3; Author: Silvio Navaretti; CompanyName: ARDUINO; DrawnBy: Silvio Navaretti; Engineer: Silvio Navaretti; Organization: ARDUINO; SheetNumber: 44; SheetTotal: 50; RevAuthor: Silvio Navaretti
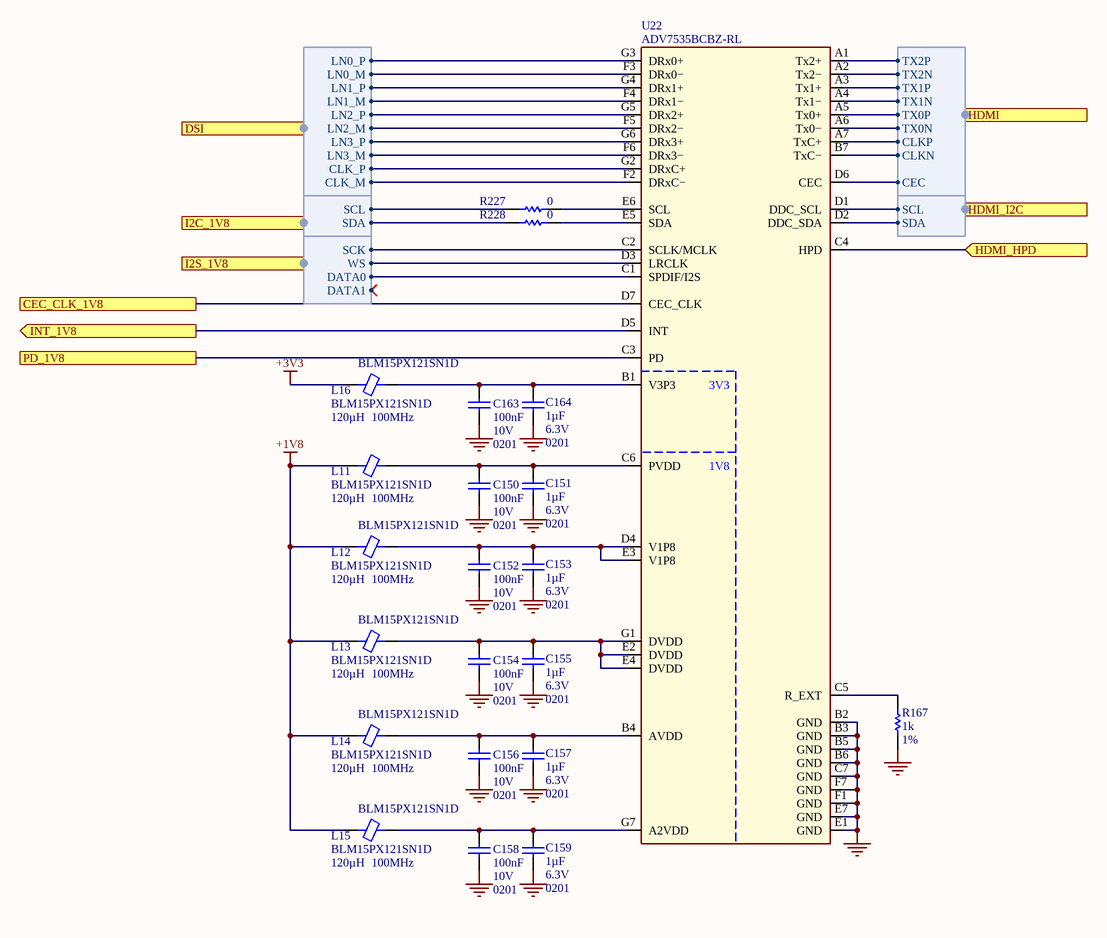
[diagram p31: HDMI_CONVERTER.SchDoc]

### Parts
C150  value 100nF  Voltage: 10V  Case Code (Imperial): 0201  [CAP-0201]  (hidden comment: CL03A104KP3NNNC)
C151  value 1µF  Voltage: 6.3V  Case Code (Imperial): 0201  [CAP-0201]  (hidden comment: GRM033R60J105MEA2D)
C152  value 100nF  Voltage: 10V  Case Code (Imperial): 0201  [CAP-0201]  (hidden comment: CL03A104KP3NNNC)
C153  value 1µF  Voltage: 6.3V  Case Code (Imperial): 0201  [CAP-0201]  (hidden comment: GRM033R60J105MEA2D)
C154  value 100nF  Voltage: 10V  Case Code (Imperial): 0201  [CAP-0201]  (hidden comment: CL03A104KP3NNNC)
C155  value 1µF  Voltage: 6.3V  Case Code (Imperial): 0201  [CAP-0201]  (hidden comment: GRM033R60J105MEA2D)
C156  value 100nF  Voltage: 10V  Case Code (Imperial): 0201  [CAP-0201]  (hidden comment: CL03A104KP3NNNC)
C157  value 1µF  Voltage: 6.3V  Case Code (Imperial): 0201  [CAP-0201]  (hidden comment: GRM033R60J105MEA2D)
C158  value 100nF  Voltage: 10V  Case Code (Imperial): 0201  [CAP-0201]  (hidden comment: CL03A104KP3NNNC)
C159  value 1µF  Voltage: 6.3V  Case Code (Imperial): 0201  [CAP-0201]  (hidden comment: GRM033R60J105MEA2D)
C163  value 100nF  Voltage: 10V  Case Code (Imperial): 0201  [CAP-0201]  (hidden comment: CL03A104KP3NNNC)
C164  value 1µF  Voltage: 6.3V  Case Code (Imperial): 0201  [CAP-0201]  (hidden comment: GRM033R60J105MEA2D)
L11  BLM15PX121SN1D  Inductance: 120µH  Test Frequency: 100MHz  [L-0402]
L12  BLM15PX121SN1D  Inductance: 120µH  Test Frequency: 100MHz  [L-0402]
L13  BLM15PX121SN1D  Inductance: 120µH  Test Frequency: 100MHz  [L-0402]
L14  BLM15PX121SN1D  Inductance: 120µH  Test Frequency: 100MHz  [L-0402]
L15  BLM15PX121SN1D  Inductance: 120µH  Test Frequency: 100MHz  [L-0402]
L16  BLM15PX121SN1D  Inductance: 120µH  Test Frequency: 100MHz  [L-0402]
R167  value 1k  Tolerance: 1%  [RES-0201]  (hidden comment: RC0201FR-071KL)
R227  value 0  [RES-0201]  (hidden comment: CRCW02010000Z0ED)
R228  value 0  [RES-0201]  (hidden comment: CRCW02010000Z0ED)
U22  ADV7535BCBZ-RL  [Analog Devices CB-49-1 WLCSP49 7x7 pitch 0.5mm 3.5x3.5mm]

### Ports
CEC_CLK_1V8, DSI (harness MIPI_4LANES), HDMI (harness HDMI), HDMI_HPD (in), HDMI_I2C (harness I2C), I2C_1V8 (harness I2C), I2S_1V8 (harness SOM_MD_I2S), INT_1V8 (out), PD_1V8

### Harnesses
I2C: SDA, SCL
MIPI_4LANES: LN3_M, LN2_M, LN2_P, LN0_M, LN0_P, CLK_M, CLK_P, LN1_M, LN1_P, LN3_P
HDMI: TX2P, TX2N, TX1P, TX1N, TX0P, TX0N, CLKP, CLKN, CEC
SOM_MD_I2S: SCK, WS, DATA0, DATA1

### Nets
+1V8: L11.1 L12.1 L13.1 L14.1 L15.1
+3V3: L16.1
GND: C150.1 C151.1 C152.1 C153.1 C154.1 C155.1 C156.1 C157.1 C158.1 C159.1 C163.1 C164.1 R167.1 U22.B2(GND) U22.B3(GND) U22.B5(GND) U22.B6(GND) U22.C7(GND) U22.E1(GND) U22.E7(GND) U22.F1(GND) U22.F7(GND)
B_CLK_N: U22.F2(DRxC−) ; port DSI.CLK_M
B_CLK_P: U22.G2(DRxC+) ; port DSI.CLK_P
B_LN0_N: U22.F3(DRx0−) ; port DSI.LN0_M
B_LN0_P: U22.G3(DRx0+) ; port DSI.LN0_P
B_LN1_N: U22.F4(DRx1−) ; port DSI.LN1_M
B_LN1_P: U22.G4(DRx1+) ; port DSI.LN1_P
B_LN2_N: U22.F5(DRx2−) ; port DSI.LN2_M
B_LN2_P: U22.G5(DRx2+) ; port DSI.LN2_P
B_LN3_N: U22.F6(DRx3−) ; port DSI.LN3_M
B_LN3_P: U22.G6(DRx3+) ; port DSI.LN3_P
HDMI_CLK_N: U22.B7(TxC−) ; port HDMI.CLKN
HDMI_CLK_P: U22.A7(TxC+) ; port HDMI.CLKP
HDMI_TX0_N: U22.A6(Tx0−) ; port HDMI.TX0N
HDMI_TX0_P: U22.A5(Tx0+) ; port HDMI.TX0P
HDMI_TX1_N: U22.A4(Tx1−) ; port HDMI.TX1N
HDMI_TX1_P: U22.A3(Tx1+) ; port HDMI.TX1P
HDMI_TX2_N: U22.A2(Tx2−) ; port HDMI.TX2N
HDMI_TX2_P: U22.A1(Tx2+) ; port HDMI.TX2P
MD_GPIO_45: R228.2 ; port I2C_1V8.SDA
MD_GPIO_46: R227.2 ; port I2C_1V8.SCL
MD_GPIO_93: U22.D5(INT) ; port INT_1V8
MD_LPASS_GPIO_125: U22.C2(SCLK/MCLK) ; port I2S_1V8.SCK
MD_LPASS_GPIO_126: U22.D3(LRCLK) ; port I2S_1V8.WS
MD_LPASS_GPIO_127: U22.C1(SPDIF/I2S) ; port I2S_1V8.DATA0
NetC150_2: C150.2 C151.2 L11.2 U22.C6(PVDD)
NetC152_2: C152.2 C153.2 L12.2 U22.D4(V1P8) U22.E3(V1P8)
NetC154_2: C154.2 C155.2 L13.2 U22.E2(DVDD) U22.E4(DVDD) U22.G1(DVDD)
NetC156_2: C156.2 C157.2 L14.2 U22.B4(AVDD)
NetC158_2: C158.2 C159.2 L15.2 U22.G7(A2VDD)
NetC163_2: C163.2 C164.2 L16.2 U22.B1(V3P3)
NetD16_1: U22.D6(CEC) ; port HDMI.CEC
NetD16_2: U22.D1(DDC_SCL) ; port HDMI_I2C.SCL
NetD16_4: U22.C4(HPD) ; port HDMI_HPD
NetD16_5: U22.D2(DDC_SDA) ; port HDMI_I2C.SDA
NetR167_2: R167.2 U22.C5(R_EXT)
NetR227_1: R227.1 U22.E6(SCL)
NetR228_1: R228.1 U22.E5(SDA)
NetU22_C3: U22.C3(PD) ; port PD_1V8
NetU22_D7: U22.D7(CEC_CLK) ; port CEC_CLK_1V8

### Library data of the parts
C150 C152 C154 C156 C158 C163 = C0113-A.6: as C134 on sheet AUDIO_CODEC
C151 C153 C155 C157 C159 C164 = C0002-A.15: as C109 on sheet AUDIO_CODEC
L11-L16 = I0028-A.10: as L17 on sheet AUDIO_CODEC
R167 = R0195-A.22: as R270 on sheet AUDIO_CODEC
R227 R228 = R0140-A.21: as R277-R283 on sheet AUDIO_CODEC
U22 = U0508-A.3: IC DSI to HDMI converter, WLCSP49 3.5x3.5mm; Manufacturer: Analog Devices; Code Arduino: U0508

## Sheet MIPI_MUX.SchDoc: MIPI MUX
size A3; Author: Silvio Navaretti; CompanyName: ARDUINO; DrawnBy: Silvio Navaretti; Engineer: Silvio Navaretti; Organization: ARDUINO; SheetNumber: 42; SheetTotal: 51; RevAuthor: Silvio Navaretti
Used 3 times, as channels U_MIPI/U_MIPI_MUX, U_MIPI/U_MIPI_MUX, U_MIPI/U_MIPI_MUX. Parts and nets are listed once, with the designators drawn on the sheet.
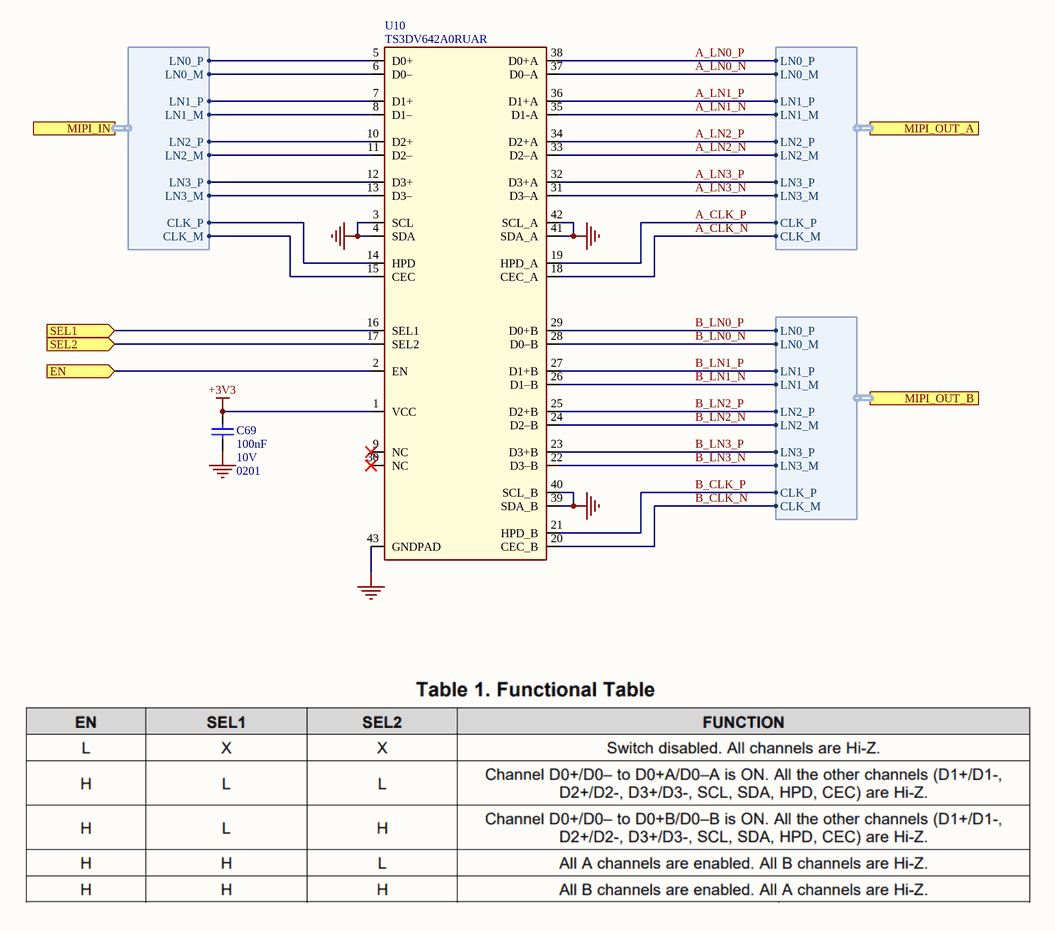
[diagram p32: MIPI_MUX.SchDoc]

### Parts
C69  value 100nF  Voltage: 10V  Case Code (Imperial): 0201  [CAP-0201]  (hidden comment: CL03A104KP3NNNC)
U10  TS3DV642A0RUAR  [TI RUA0042A WQFN 42 pin pitch 0.5mm 3.5x9mm]

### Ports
EN (in), MIPI_IN (harness MIPI_4LANES), MIPI_OUT_A (harness MIPI_4LANES), MIPI_OUT_B (harness MIPI_4LANES), SEL1 (in), SEL2 (in)

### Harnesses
MIPI_4LANES: LN3_M, LN2_M, LN2_P, LN0_M, LN0_P, CLK_M, CLK_P, LN1_M, LN1_P, LN3_P

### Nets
+3V3: C69.2 U10.1(VCC)
GND: C69.1 U10.3(SCL) U10.4(SDA) U10.39(SDA_B) U10.40(SCL_B) U10.41(SDA_A) U10.42(SCL_A) U10.43(GNDPAD)
A_CLK_N: U10.18(CEC_A) ; port MIPI_OUT_A.CLK_M
A_CLK_P: U10.19(HPD_A) ; port MIPI_OUT_A.CLK_P
A_LN0_N: U10.37(D0–A) ; port MIPI_OUT_A.LN0_M
A_LN0_P: U10.38(D0+A) ; port MIPI_OUT_A.LN0_P
A_LN1_N: U10.35(D1-A) ; port MIPI_OUT_A.LN1_M
A_LN1_P: U10.36(D1+A) ; port MIPI_OUT_A.LN1_P
A_LN2_N: U10.33(D2–A) ; port MIPI_OUT_A.LN2_M
A_LN2_P: U10.34(D2+A) ; port MIPI_OUT_A.LN2_P
A_LN3_N: U10.31(D3–A) ; port MIPI_OUT_A.LN3_M
A_LN3_P: U10.32(D3+A) ; port MIPI_OUT_A.LN3_P
B_CLK_N: U10.20(CEC_B) ; port MIPI_OUT_B.CLK_M
B_CLK_P: U10.21(HPD_B) ; port MIPI_OUT_B.CLK_P
B_LN0_N: U10.28(D0–B) ; port MIPI_OUT_B.LN0_M
B_LN0_P: U10.29(D0+B) ; port MIPI_OUT_B.LN0_P
B_LN1_N: U10.26(D1–B) ; port MIPI_OUT_B.LN1_M
B_LN1_P: U10.27(D1+B) ; port MIPI_OUT_B.LN1_P
B_LN2_N: U10.24(D2–B) ; port MIPI_OUT_B.LN2_M
B_LN2_P: U10.25(D2+B) ; port MIPI_OUT_B.LN2_P
B_LN3_N: U10.22(D3–B) ; port MIPI_OUT_B.LN3_M
B_LN3_P: U10.23(D3+B) ; port MIPI_OUT_B.LN3_P
EN: U10.2(EN) ; port EN
SEL1: U10.16(SEL1) ; port SEL1
SEL2: U10.17(SEL2) ; port SEL2
NetU10_5: U10.5(D0+) ; port MIPI_IN.LN0_P
NetU10_6: U10.6(D0–) ; port MIPI_IN.LN0_M
NetU10_7: U10.7(D1+) ; port MIPI_IN.LN1_P
NetU10_8: U10.8(D1–) ; port MIPI_IN.LN1_M
NetU10_10: U10.10(D2+) ; port MIPI_IN.LN2_P
NetU10_11: U10.11(D2–) ; port MIPI_IN.LN2_M
NetU10_12: U10.12(D3+) ; port MIPI_IN.LN3_P
NetU10_13: U10.13(D3–) ; port MIPI_IN.LN3_M
NetU10_14: U10.14(HPD) ; port MIPI_IN.CLK_P
NetU10_15: U10.15(CEC) ; port MIPI_IN.CLK_M

Not connected (* = marked no-connect by the designer): U10 9(NC)* 30(NC)*

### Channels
U_MIPI/U_MIPI_MUX: designators end in _1; ports EN=NetR393_1 SEL1=NetR394_1 SEL2=NetR112_1
U_MIPI/U_MIPI_MUX: designators end in _2; ports EN=NetR162_2 SEL1=NetR268_1 SEL2=MD_GPIO_24
U_MIPI/U_MIPI_MUX: designators end in _3; ports EN=NetR386_2 SEL1=NetR392_1 SEL2=MD_GPIO_41

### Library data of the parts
C69 = C0113-A.6: as C134 on sheet AUDIO_CODEC
U10 = U0522-A.2: IC MUX SWITCH 6GHz, 12 channel 2:1 bidirectional switch, port A 6.9GHz port B 7.5GHz, Vcc 2.6V to 4.5V, WQFN42 9x3.5mm; Manufacturer: Texas Instruments; Code Arduino: U0522

## Sheet MIPI_FLAT_22PIN.SchDoc: MIPI FLAT 22 PIN
size A3; Author: Silvio Navaretti; CompanyName: ARDUINO; DrawnBy: Silvio Navaretti; Engineer: Silvio Navaretti; Organization: ARDUINO; SheetNumber: 43; SheetTotal: 51; RevAuthor: Silvio Navaretti
Used 3 times, as channels U_MIPI/U_MIPI_FLAT_22PIN, U_MIPI/U_MIPI_FLAT_22PIN, U_MIPI/U_MIPI_FLAT_22PIN. Parts and nets are listed once, with the designators drawn on the sheet.
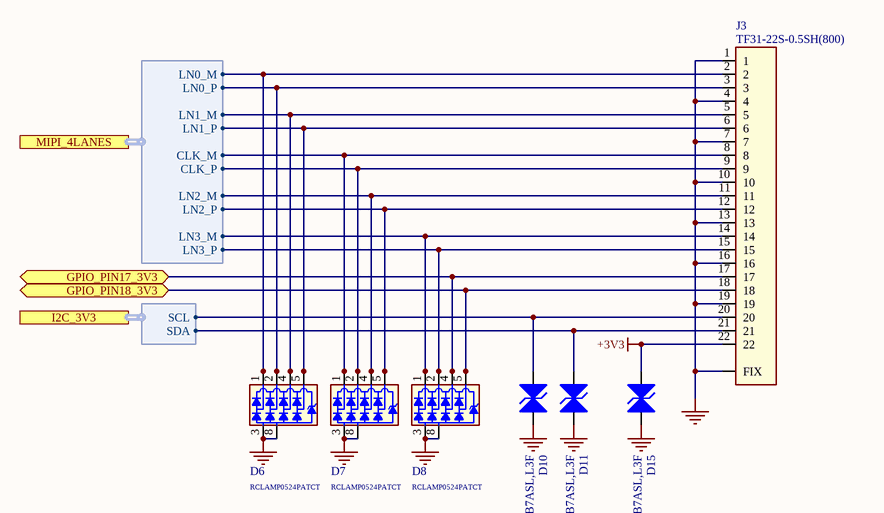
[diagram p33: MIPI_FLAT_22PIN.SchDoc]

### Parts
D6  RCLAMP0524PATCT  [SLP2510P8]
D7  RCLAMP0524PATCT  [SLP2510P8]
D8  RCLAMP0524PATCT  [SLP2510P8]
D10  DF2B7ASL,L3F  [DF2B7ASL,L3F]
D11  DF2B7ASL,L3F  [DF2B7ASL,L3F]
D15  DF2B7ASL,L3F  [DF2B7ASL,L3F]
J3  TF31-22S-0.5SH(800)  [TF31-22S-0.5SH(800)]

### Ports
GPIO_PIN17_3V3 (bidir), GPIO_PIN18_3V3 (bidir), I2C_3V3 (harness I2C), MIPI_4LANES (harness MIPI_4LANES)

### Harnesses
MIPI_4LANES: LN3_M, LN2_M, LN2_P, LN0_M, LN0_P, CLK_M, CLK_P, LN1_M, LN1_P, LN3_P
I2C: SDA, SCL

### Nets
+3V3: D15.2(A2) J3.22
GND: D6.3 D6.8 D7.3 D7.8 D8.3 D8.8 D10.1(A1) D11.1(A1) D15.1(A1) J3.1 J3.4 J3.7 J3.10 J3.13 J3.16 J3.19 J3.FIX
GPIO_PIN17_3V3: D8.4 D8.7 J3.17 ; port GPIO_PIN17_3V3
GPIO_PIN18_3V3: D8.5 D8.6 J3.18 ; port GPIO_PIN18_3V3
NetD6_1: D6.1 D6.10 J3.2 ; port MIPI_4LANES.LN0_M
NetD6_2: D6.2 D6.9 J3.3 ; port MIPI_4LANES.LN0_P
NetD6_4: D6.4 D6.7 J3.5 ; port MIPI_4LANES.LN1_M
NetD6_5: D6.5 D6.6 J3.6 ; port MIPI_4LANES.LN1_P
NetD7_1: D7.1 D7.10 J3.8 ; port MIPI_4LANES.CLK_M
NetD7_2: D7.2 D7.9 J3.9 ; port MIPI_4LANES.CLK_P
NetD7_4: D7.4 D7.7 J3.11 ; port MIPI_4LANES.LN2_M
NetD7_5: D7.5 D7.6 J3.12 ; port MIPI_4LANES.LN2_P
NetD8_1: D8.1 D8.10 J3.14 ; port MIPI_4LANES.LN3_M
NetD8_2: D8.2 D8.9 J3.15 ; port MIPI_4LANES.LN3_P
NetD10_2: D10.2(A2) J3.20 ; port I2C_3V3.SCL
NetD11_2: D11.2(A2) J3.21 ; port I2C_3V3.SDA

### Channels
U_MIPI/U_MIPI_FLAT_22PIN: designators end in _1; ports GPIO_PIN17_3V3=FLAT1_GPIO_PIN17_3V3 GPIO_PIN18_3V3=NetD8_1_5
U_MIPI/U_MIPI_FLAT_22PIN: designators end in _2; ports GPIO_PIN17_3V3=FLAT0_GPIO_PIN17_3V3 GPIO_PIN18_3V3=NetD8_2_5
U_MIPI/U_MIPI_FLAT_22PIN: designators end in _3; ports GPIO_PIN17_3V3=FLAT2_GPIO_PIN17_3V3 GPIO_PIN18_3V3=NetD8_3_5

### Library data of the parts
D6-D8 = D0097-A.6: as D13 on sheet HDMI_CONNECTOR
D10 D11 D15 = D0099-5: as D12 on sheet HDMI_CONNECTOR
J3 = J0553-A.2: CONN FFC/FPC Connector, 22 Contact(s), 1 Row(s), BOTTOM CONTACT, Female, Right Angle, 0.5mm Pitch; Manufacturer: Hirose; Code Arduino: J0553

## Sheet PUSHBUTTONS.SchDoc: PUSHBUTTON
size A3; SheetNumber: 49; SheetTotal: 51
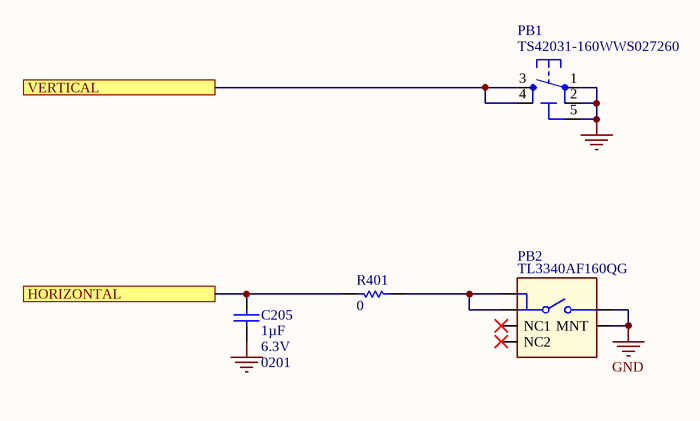
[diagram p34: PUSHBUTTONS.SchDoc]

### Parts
C205  value 1µF  Voltage: 6.3V  Case Code (Imperial): 0201  [CAP-0201]  (hidden comment: GRM033R60J105MEA2D)
PB1  TS42031-160WWS027260  [TS42]
PB2  TL3340AF160QG  [TL3340AF160QG-Footprint-1]
R401  value 0  [RES-0201]  (hidden comment: CRCW02010000Z0ED)

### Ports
HORIZONTAL, VERTICAL

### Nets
GND: C205.1 PB1.1 PB1.2 PB1.5(5-GND) PB2.2 PB2.MNT
MD_GPIO_79: C205.2 R401.1 ; port HORIZONTAL
NetPB1_3: PB1.3 PB1.4 ; port VERTICAL
NetPB2_1: PB2.1 PB2.3 R401.2

Not connected (* = marked no-connect by the designer): PB2 NC1* NC2*

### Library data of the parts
C205 = C0002-A.15: as C109 on sheet AUDIO_CODEC
PB1 = B0005-A.11: PUSHBUTTON SMD 6x6 5 PINS; Manufacturer: C&K; Code Arduino: 0946
PB2 = B0013-A.8: PUSHBUTTON SMD VERTICAL ANCHORS 4x3.4mm; Manufacturer: E-Switch; Code Arduino: B0013
R401 = R0140-A.21: RES CHIP 0201 0R; Manufacturer: Vishay; Tolerance: 0%; Temperature coefficient: 0ppm; Power: 50mW; Code Arduino: R0140

## Sheet HEADERS_JOMEGA.SchDoc: JOMEGA
size A3; SheetNumber: 22; SheetTotal: 51
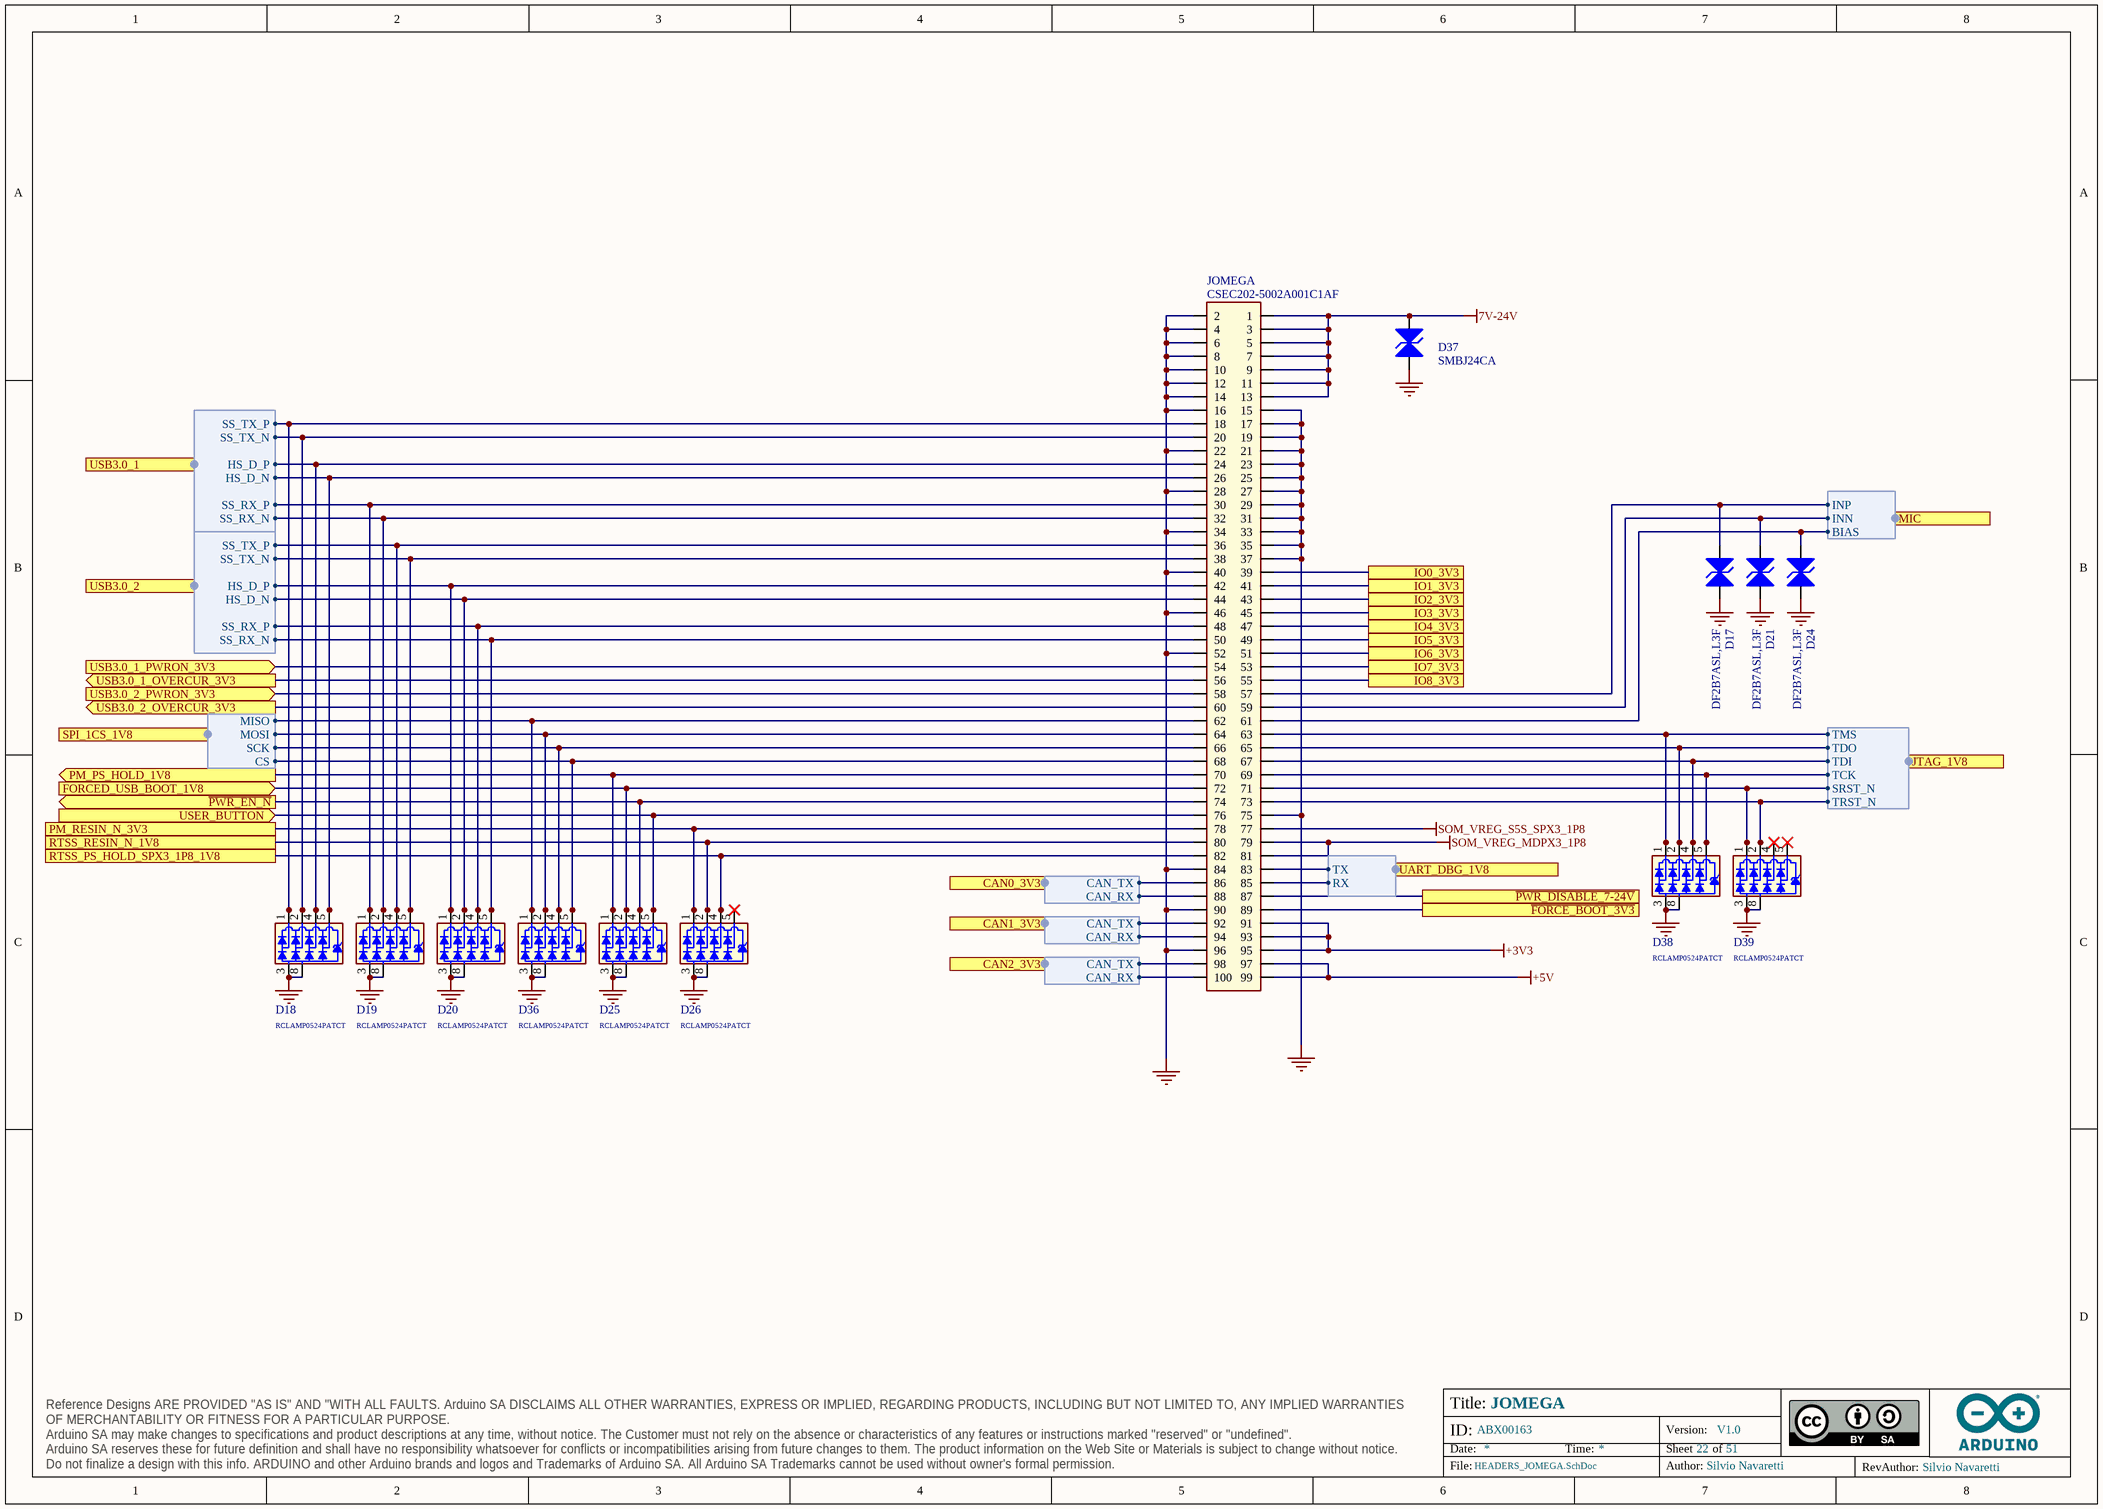
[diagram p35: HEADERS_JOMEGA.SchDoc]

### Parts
D17  DF2B7ASL,L3F  [DF2B7ASL,L3F]
D18  RCLAMP0524PATCT  [SLP2510P8]
D19  RCLAMP0524PATCT  [SLP2510P8]
D20  RCLAMP0524PATCT  [SLP2510P8]
D21  DF2B7ASL,L3F  [DF2B7ASL,L3F]
D24  DF2B7ASL,L3F  [DF2B7ASL,L3F]
D25  RCLAMP0524PATCT  [SLP2510P8]
D26  RCLAMP0524PATCT  [SLP2510P8]
D36  RCLAMP0524PATCT  [SLP2510P8]
D37  SMBJ24CA  [SMB_NOPOLARITY]
D38  RCLAMP0524PATCT  [SLP2510P8]
D39  RCLAMP0524PATCT  [SLP2510P8]
JOMEGA  CSEC202-5002A001C1AF  [CSEC202-5002A001C1AF]

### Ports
CAN0_3V3 (out, harness CAN), CAN1_3V3 (out, harness CAN), CAN2_3V3 (out, harness CAN), FORCED_USB_BOOT_1V8 (in), IO0_3V3, IO1_3V3, IO2_3V3, IO3_3V3, IO4_3V3, IO5_3V3, IO6_3V3, IO7_3V3, IO8_3V3, JTAG_1V8 (out, harness SOM_SAIL_JTAG), MIC (out, harness MIC), PM_PS_HOLD_1V8 (out), PM_RESIN_N_3V3, RTSS_PS_HOLD_SPX3_1P8_1V8, RTSS_RESIN_N_1V8, SPI_1CS_1V8 (in, harness SPI), UART_DBG_1V8 (harness UART), USB3.0_1 (out, harness SOM_MD_USB0), USB3.0_1_OVERCUR_3V3 (out), USB3.0_1_PWRON_3V3 (in), USB3.0_2 (out, harness SOM_MD_USB0), USB3.0_2_OVERCUR_3V3 (out), USB3.0_2_PWRON_3V3 (in), USER_BUTTON (in), ~{FORCE_BOOT_3V3}, ~{PWR_DISABLE_7-24V}, ~{PWR_EN_N} (out)

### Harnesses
MIC: INP, INN, BIAS
SOM_SAIL_JTAG: TMS, TDO, TDI, TCK, SRST_N, TRST_N
SOM_MD_USB0: SS_TX_N, SS_TX_P, HS_D_P, HS_D_N, SS_RX_P, SS_RX_N
SPI: SCK, MISO, MOSI, CS
CAN: CAN_TX, CAN_RX
UART: TX, RX

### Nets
7V-24V: D37.2(A2) JOMEGA.1 JOMEGA.3 JOMEGA.5 JOMEGA.7 JOMEGA.9 JOMEGA.11 JOMEGA.13
+3V3: JOMEGA.91 JOMEGA.93 JOMEGA.95
+5V: JOMEGA.97 JOMEGA.99
GND: D17.1(A1) D18.3 D18.8 D19.3 D19.8 D20.3 D20.8 D21.1(A1) D24.1(A1) D25.3 D25.8 D26.3 D26.8 D36.3 D36.8 D37.1(A1) D38.3 D38.8 D39.3 D39.8 JOMEGA.2 JOMEGA.4 JOMEGA.6 JOMEGA.8 JOMEGA.10 JOMEGA.12 JOMEGA.14 JOMEGA.15 JOMEGA.16 JOMEGA.17 JOMEGA.19 JOMEGA.21 JOMEGA.22 JOMEGA.23 JOMEGA.25 JOMEGA.27 JOMEGA.28 JOMEGA.29 JOMEGA.31 JOMEGA.33 JOMEGA.34 JOMEGA.35 JOMEGA.37 JOMEGA.40 JOMEGA.46 JOMEGA.52 JOMEGA.75 JOMEGA.84 JOMEGA.90 JOMEGA.96
SOM_VREG_MDPX3_1P8: JOMEGA.79 JOMEGA.81
SOM_VREG_S5S_SPX3_1P8: JOMEGA.77
FORCE_BOOT_3V3: JOMEGA.89 ; port ~{FORCE_BOOT_3V3}
MD_GPIO_37: D36.4 D36.7 JOMEGA.66 ; port SPI_1CS_1V8.SCK
MD_GPIO_38: D36.5 D36.6 JOMEGA.68 ; port SPI_1CS_1V8.CS
MD_GPIO_39: D36.1 D36.10 JOMEGA.62 ; port SPI_1CS_1V8.MISO
MD_GPIO_40: D36.2 D36.9 JOMEGA.64 ; port SPI_1CS_1V8.MOSI
MD_GPIO_43: JOMEGA.83 ; port UART_DBG_1V8.TX
MD_GPIO_44: JOMEGA.85 ; port UART_DBG_1V8.RX
MD_GPIO_52: D25.2 D25.9 JOMEGA.72 ; port FORCED_USB_BOOT_1V8
MD_GPIO_79: D25.5 D25.6 JOMEGA.76 ; port USER_BUTTON
MIC_IN5_IN6.BIAS: D24.2(A2) JOMEGA.61 ; port MIC.BIAS
MIC_IN5_IN6.INN: D21.2(A2) JOMEGA.59 ; port MIC.INN
MIC_IN5_IN6.INP: D17.2(A2) JOMEGA.57 ; port MIC.INP
~{PM_RESIN_N_3V3}: D26.1 D26.10 JOMEGA.78 ; port PM_RESIN_N_3V3
~{POWER_DISABLE_7-24V}: JOMEGA.87 ; port ~{PWR_DISABLE_7-24V}
~{PWR_EN_N_3V3}: D25.4 D25.7 JOMEGA.74 ; port ~{PWR_EN_N}
PA10: JOMEGA.92 ; port CAN1_3V3.CAN_TX
PC0: JOMEGA.39 ; port IO0_3V3
PC1: JOMEGA.41 ; port IO1_3V3
PC2: JOMEGA.43 ; port IO2_3V3
PC3: JOMEGA.45 ; port IO3_3V3
PD5: JOMEGA.86 ; port CAN0_3V3.CAN_TX
PD9: JOMEGA.94 ; port CAN1_3V3.CAN_RX
PD12: JOMEGA.47 ; port IO4_3V3
PD13: JOMEGA.49 ; port IO5_3V3
PD14: JOMEGA.51 ; port IO6_3V3
PD15: JOMEGA.53 ; port IO7_3V3
PF6: JOMEGA.98 ; port CAN2_3V3.CAN_TX
PF7: JOMEGA.100 ; port CAN2_3V3.CAN_RX
PI2: JOMEGA.55 ; port IO8_3V3
PI9: JOMEGA.88 ; port CAN0_3V3.CAN_RX
PM_PS_HOLD: D25.1 D25.10 JOMEGA.70 ; port PM_PS_HOLD_1V8
RTSS_PS_HOLD_SPX3_1P8: D26.4 D26.7 JOMEGA.82 ; port RTSS_PS_HOLD_SPX3_1P8_1V8
RTSS_RESIN_N: D26.2 D26.9 JOMEGA.80 ; port RTSS_RESIN_N_1V8
SAIL_JTAG.SRST_N: D39.1 D39.10 JOMEGA.71 ; port JTAG_1V8.SRST_N
SAIL_JTAG.TCK: D38.5 D38.6 JOMEGA.69 ; port JTAG_1V8.TCK
SAIL_JTAG.TDI: D38.4 D38.7 JOMEGA.67 ; port JTAG_1V8.TDI
SAIL_JTAG.TDO: D38.2 D38.9 JOMEGA.65 ; port JTAG_1V8.TDO
SAIL_JTAG.TMS: D38.1 D38.10 JOMEGA.63 ; port JTAG_1V8.TMS
SAIL_JTAG.TRST_N: D39.2 D39.9 JOMEGA.73 ; port JTAG_1V8.TRST_N
USB1_CAP_SSTX_N: D18.2 D18.9 JOMEGA.20 ; port USB3.0_1.SS_TX_N
USB1_CAP_SSTX_P: D18.1 D18.10 JOMEGA.18 ; port USB3.0_1.SS_TX_P
USB1_D_N: D18.5 D18.6 JOMEGA.26 ; port USB3.0_1.HS_D_N
USB1_D_P: D18.4 D18.7 JOMEGA.24 ; port USB3.0_1.HS_D_P
USB1_SSRX_N: D19.2 D19.9 JOMEGA.32 ; port USB3.0_1.SS_RX_N
USB1_SSRX_P: D19.1 D19.10 JOMEGA.30 ; port USB3.0_1.SS_RX_P
USB3_CAP_SSTX_N: D19.5 D19.6 JOMEGA.38 ; port USB3.0_2.SS_TX_N
USB3_CAP_SSTX_P: D19.4 D19.7 JOMEGA.36 ; port USB3.0_2.SS_TX_P
USB3_D_N: D20.2 D20.9 JOMEGA.44 ; port USB3.0_2.HS_D_N
USB3_D_P: D20.1 D20.10 JOMEGA.42 ; port USB3.0_2.HS_D_P
USB3_SSRX_N: D20.5 D20.6 JOMEGA.50 ; port USB3.0_2.SS_RX_N
USB3_SSRX_P: D20.4 D20.7 JOMEGA.48 ; port USB3.0_2.SS_RX_P
NetD26_5: D26.5 D26.6
NetD39_4: D39.4 D39.7
NetD39_5: D39.5 D39.6
NetJOMEGA_54: JOMEGA.54 ; port USB3.0_1_PWRON_3V3
NetJOMEGA_56: JOMEGA.56 ; port USB3.0_1_OVERCUR_3V3
NetJOMEGA_58: JOMEGA.58 ; port USB3.0_2_PWRON_3V3
NetJOMEGA_60: JOMEGA.60 ; port USB3.0_2_OVERCUR_3V3

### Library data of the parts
D17 D21 D24 = D0099-5: as D12 on sheet HDMI_CONNECTOR
D18-D20 D25 D26 D36 D38 D39 = D0097-A.6: as D13 on sheet HDMI_CONNECTOR
D37 = D0070-A.2: TVS BIDIRECTIONAL SMD Vr 24V, Vbr min 26.7V, 600W, SMB; Manufacturer: Littlefuse; V(BR) Typ (V): 26.7; Code Arduino: D0070
JOMEGA = J0574-A.2: CONN HEADER FEMALE VERTICAL SMD 1.27mm 2x50 POS heigth 4.4mm; Manufacturer: Greenconn; Code Arduino: J0574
